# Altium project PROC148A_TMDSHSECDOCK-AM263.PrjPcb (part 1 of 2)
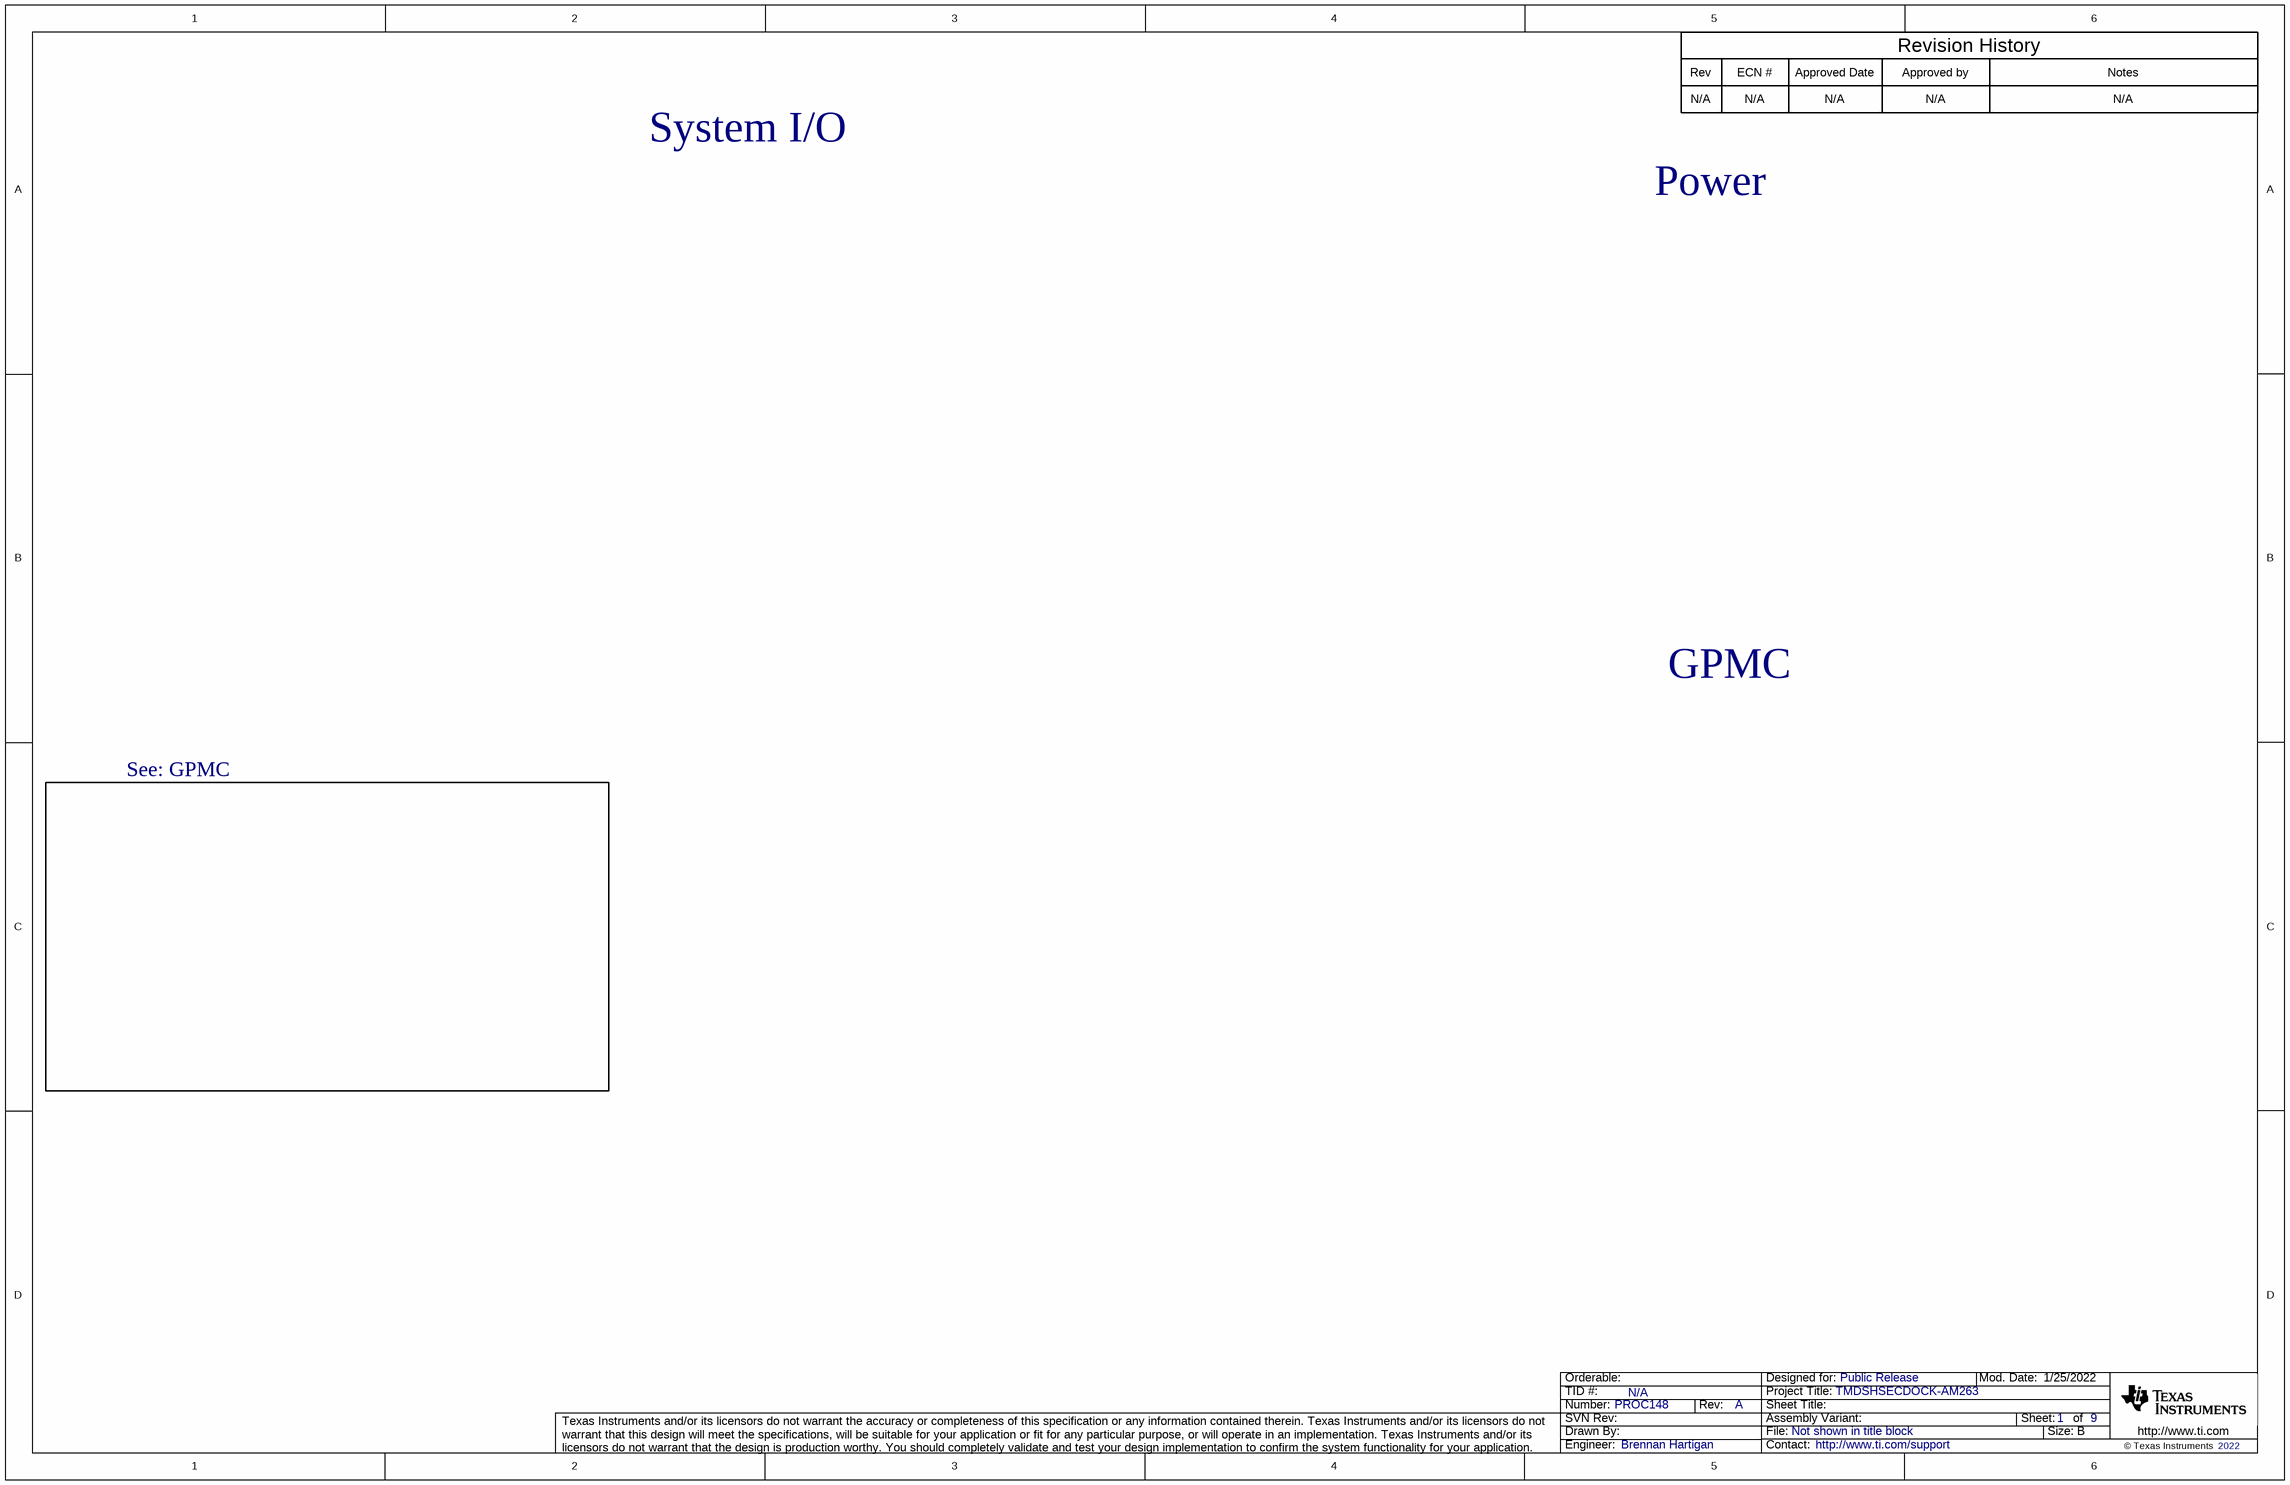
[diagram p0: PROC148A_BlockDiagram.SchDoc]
CopyrightYear: 2022; PCB_Layout: Mistral; PCB_Rev: A; PRJ_Customer: Public Release; PRJ_Engineer: Brennan Hartigan; PRJ_Number: PROC148; PRJ_Title: TMDSHSECDOCK-AM263; SCH_Rev: A; TechSupport: http://www.ti.com/support; TID: N/A
9 sheets, 287 parts. Net scope: global (net labels, ports and power ports of the same name join across sheets).
Board file: PROC148A_BRD.PcbDoc
Sheets:
  PROC148A_BlockDiagram.SchDoc
  PROC148A_PWR.SchDoc
  PROC148A_HSEC.SchDoc
  PROC148A_CAN_LIN.SchDoc
  PROC148A_HSECMUX.SchDoc
  PROC148A_PSRAM.SchDoc
  PROC148A_GPMC_interface.SchDoc
  PROC148A_JTAG_TRACE.SchDoc
  PROC148A_Hardware.SchDoc

## Sheet PROC148A_BlockDiagram.SchDoc
size 431 x 279 mm; Date: Not shown in title block; ApprovedBy: Not shown in title block; CheckedBy: Not shown in title block; Author: Not shown in title block; CompanyName: Not shown in title block; Engineer: Not shown in title block; Organization: Not shown in title block; Address1: Not shown in title block; Address2: Not shown in title block; Address3: Not shown in title block; Address4: Not shown in title block; DocumentNumber: 1; Revision: Use project parameter SCH_Rev; SheetNumber: 1; SheetTotal: 9; PageSetup: Record=PageOptions¦CenterHorizontal=True¦CenterVertical=True¦PrintScale=1.00¦XCorrection=1.00¦YCorrection=1.00¦PrintKind=0¦BorderSize=5000000¦LeftOffset=0¦BottomOffset=0¦Orientation=2¦PaperLength=1000¦PaperWidth=1000¦Scale=100¦PaperSource=15¦PrintQuality=600¦MediaType=1¦DitherType=10¦PaperKind=Letter¦PrintScaleMode=1

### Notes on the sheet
- Rev
- N/A
- ECN #
- Approved Date
- Approved by
- Revision History
- Notes
- System I/O
- Power
- GPMC
- See: GPMC

## Sheet PROC148A_PWR.SchDoc
size 431 x 279 mm; Date: Not shown in title block; ApprovedBy: Not shown in title block; CheckedBy: Not shown in title block; Author: Not shown in title block; CompanyName: Not shown in title block; Engineer: Not shown in title block; Organization: Not shown in title block; Address1: Not shown in title block; Address2: Not shown in title block; Address3: Not shown in title block; Address4: Not shown in title block; DocumentNumber: 1; Revision: Use project parameter SCH_Rev; SheetNumber: 2; SheetTotal: 9; PageSetup: Record=PageOptions¦CenterHorizontal=True¦CenterVertical=True¦PrintScale=1.00¦XCorrection=1.00¦YCorrection=1.00¦PrintKind=0¦BorderSize=5000000¦LeftOffset=0¦BottomOffset=0¦Orientation=2¦PaperLength=1000¦PaperWidth=1000¦Scale=100¦PaperSource=15¦PrintQuality=600¦MediaType=1¦DitherType=10¦PaperKind=Letter¦PrintScaleMode=1
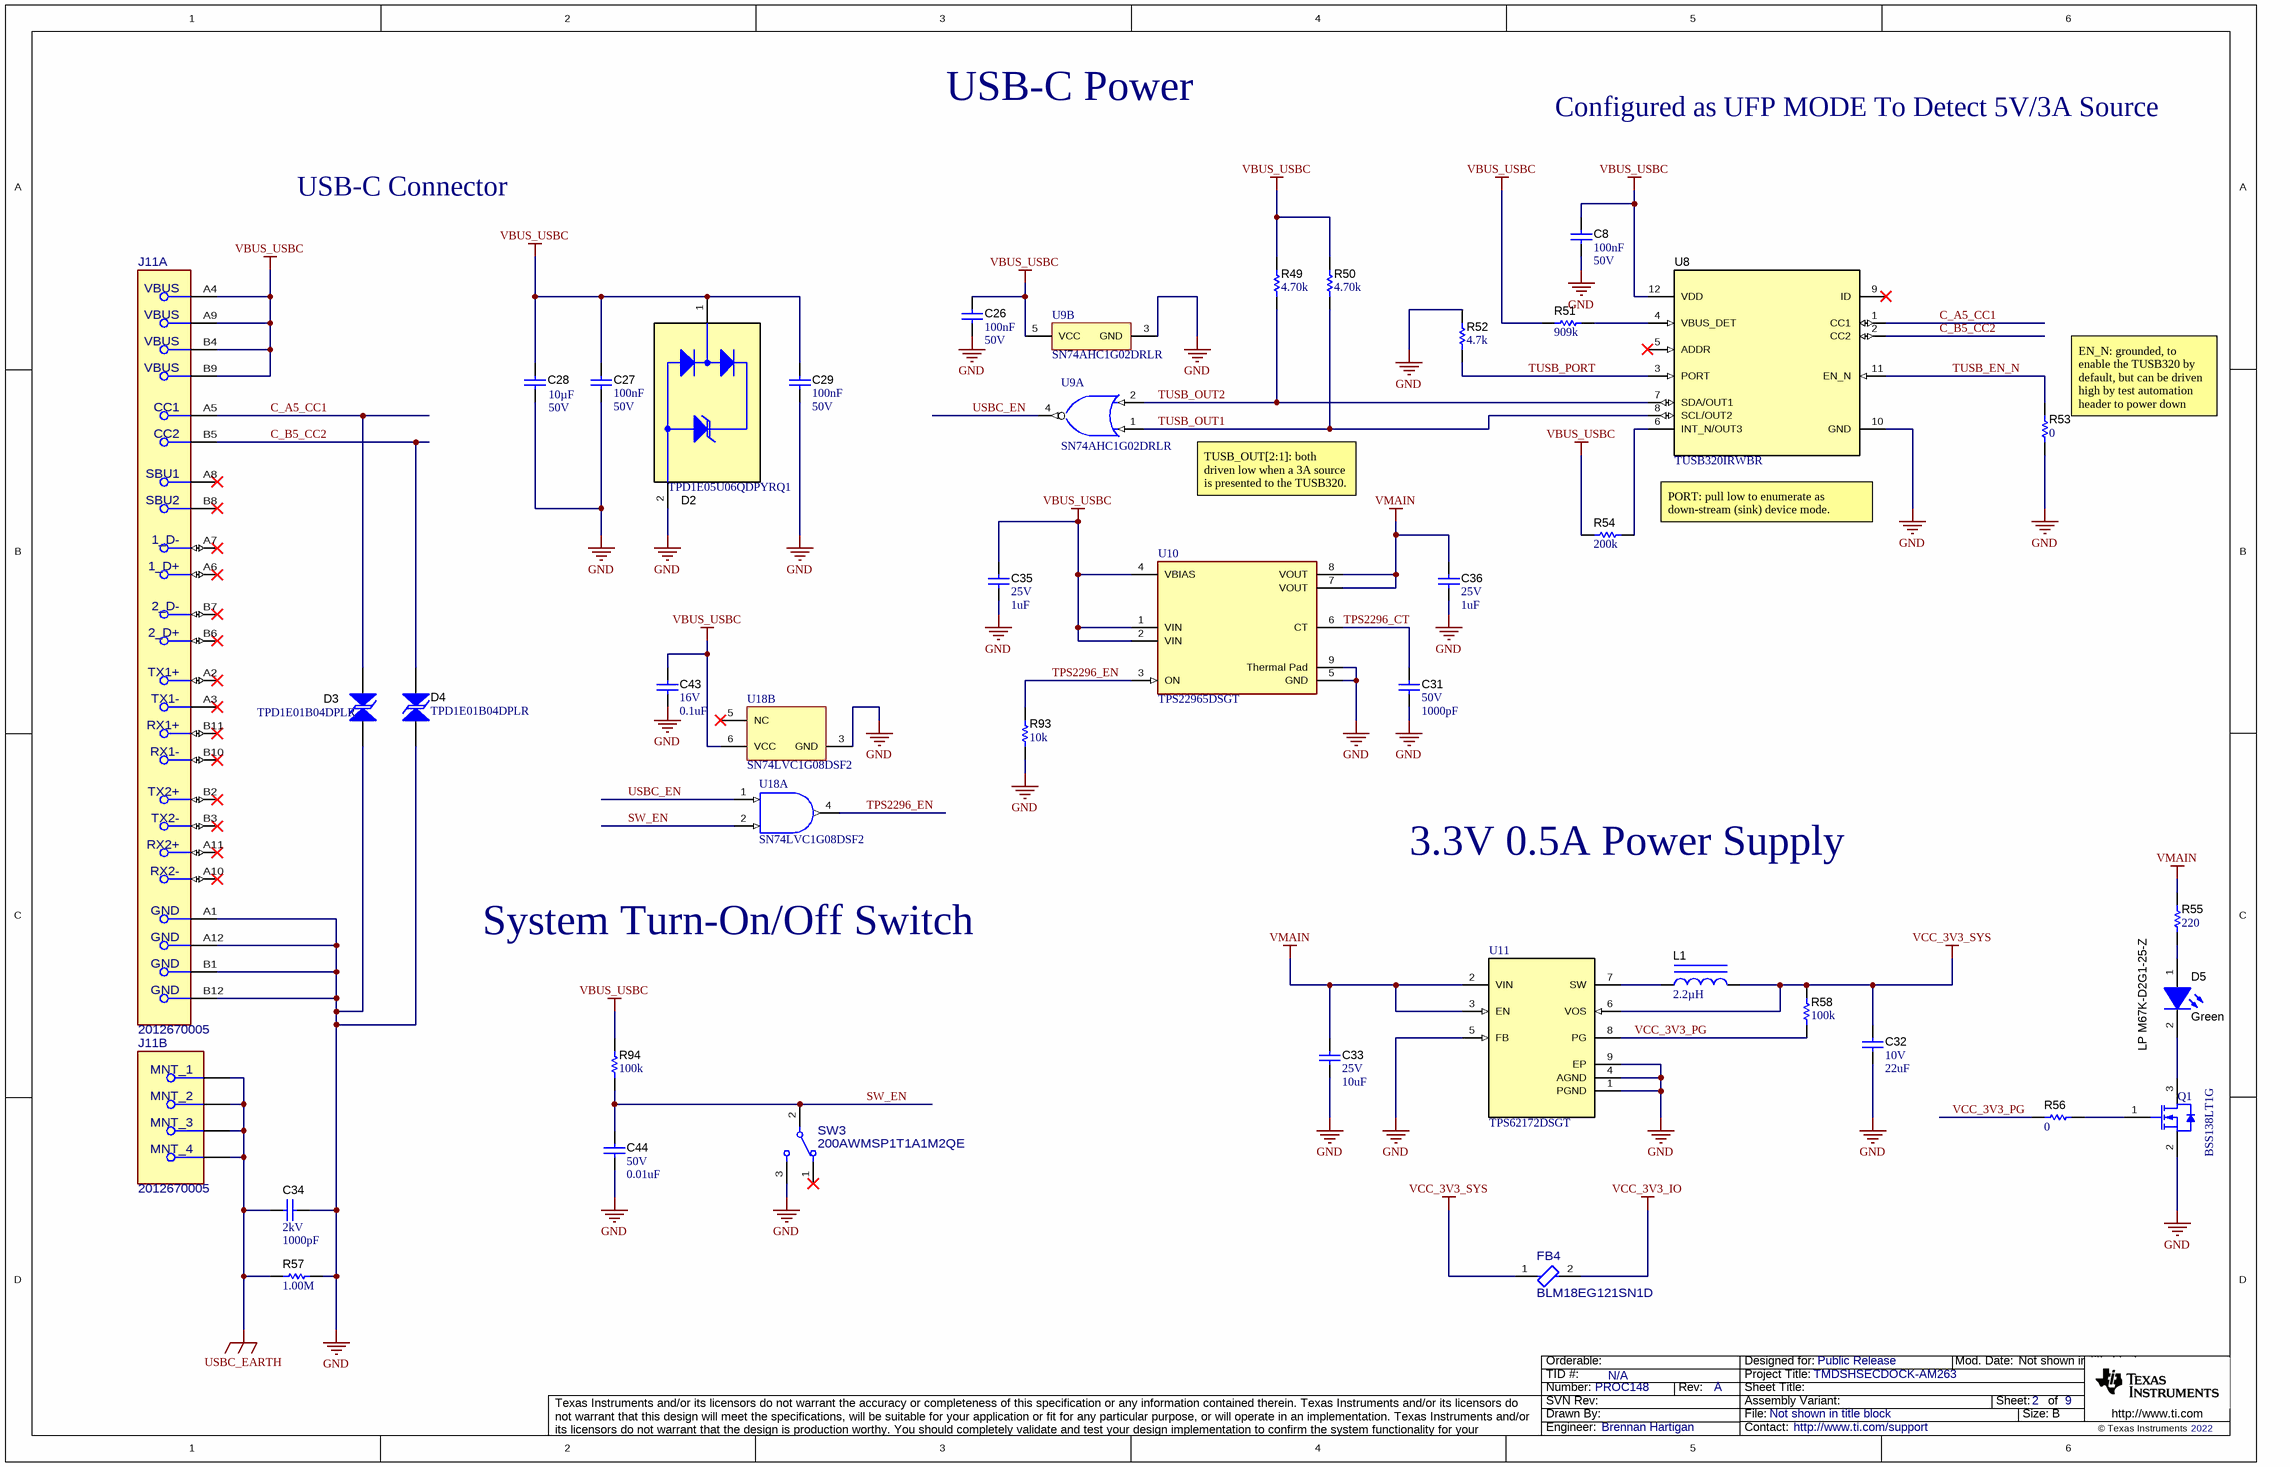
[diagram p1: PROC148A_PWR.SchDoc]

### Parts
C8  Cap_F: 100nF  VDC_V: 50V  [0805_HV]  (hidden comment: C0805C104M5RACTU)
C26  Cap_F: 100nF  VDC_V: 50V  [0805_HV]  (hidden comment: C0805C104M5RACTU)
C27  Cap_F: 100nF  VDC_V: 50V  [0805_HV]  (hidden comment: C0805C104M5RACTU)
C28  VDC_V: 50V  ValueDisplayed: 10µF  [1210_270]  (hidden comment: CL32B106KBJNNWE)
C29  Cap_F: 100nF  VDC_V: 50V  [0805_HV]  (hidden comment: C0805C104M5RACTU)
C31  VDC_V: 50V  ValueDisplayed: 1000pF  [0402]  (hidden comment: GRM1555C1H102JA01D)
C32  VDC_V: 10V  ValueDisplayed: 22uF  [1206_180]  (hidden comment: GRM31CR71A226KE15L)
C33  VDC_V: 25V  ValueDisplayed: 10uF  [0603]  (hidden comment: GRT188R61E106ME13D)
C34  VDC_V: 2kV  ValueDisplayed: 1000pF  [1808]  (hidden comment: GR442QR73D102KW01L)
C35  VDC_V: 25V  ValueDisplayed: 1uF  [0402]  (hidden comment: GRM155R61E105KA12D)
C36  VDC_V: 25V  ValueDisplayed: 1uF  [0402]  (hidden comment: GRM155R61E105KA12D)
C43  VDC_V: 16V  ValueDisplayed: 0.1uF  [0201_033]  (hidden comment: GRM033R61C104KE84D)
C44  VDC_V: 50V  ValueDisplayed: 0.01uF  [0603]  (hidden comment: GRM1885C1H103JA01D)
D2  TPD1E05U06QDPYRQ1  [DPY0002A]
D3  TPD1E01B04DPLR  [DPL0002A]
D4  TPD1E01B04DPLR  [DPL0002A]
D5  LP M67K-D2G1-25-Z  value Green  [LP-M67K_Green]
FB4  BLM18EG121SN1D  [FP-BLM18EG121SN1D_0603-MFG]
J11  2012670005  [FP-2012670005_CONN_USB_9MM39_8MM21-MFG]  (parts A,B of 2)
L1  ValueDisplayed: 2.2µH  [TFM201610ALMA]  (hidden comment: TFM201610ALMA2R2MTAA)
Q1  BSS138LT1G  [ONSC-SOT-23-3-318-08_V]
R49  ValueDisplayed: 4.70k  [0402]  (hidden comment: ERJ-2RKF4701X)
R50  ValueDisplayed: 4.70k  [0402]  (hidden comment: ERJ-2RKF4701X)
R51  ValueDisplayed: 909k  [0805_HV]  (hidden comment: ERJ-6ENF9093V)
R52  ValueDisplayed: 4.7k  [0603]  (hidden comment: CRCW06034K70JNEA)
R53  ValueDisplayed: 0  [0402]  (hidden comment: CRCW04020000Z0ED)
R54  ValueDisplayed: 200k  [0402]  (hidden comment: ERJ-2RKF2003X)
R55  ValueDisplayed: 220  [0603]  (hidden comment: CRCW0603220RJNEA)
R56  ValueDisplayed: 0  [0402]  (hidden comment: CRCW04020000Z0ED)
R57  ValueDisplayed: 1.00M  [1206]  (hidden comment: CRCW12061M00FKEA)
R58  ValueDisplayed: 100k  [0402]  (hidden comment: CRCW0402100KFKED)
R93  ValueDisplayed: 10k  [0402]  (hidden comment: CRCW040210K0JNED)
R94  ValueDisplayed: 100k  [0402]  (hidden comment: CRCW0402100KFKED)
SW3  200AWMSP1T1A1M2QE  [FP-200AWMSP1T1A1M2QE_PTH_SW_8MM13_5MM08-MFG]
U8  TUSB320IRWBR  [RWB0012A]
U9  SN74AHC1G02DRLR  [DRL0005A]  (parts A,B of 2)
U10  TPS22965DSGT  [FP-DSG0008A-MFG]
U11  TPS62172DSGT  [DSG0008A]
U18  SN74LVC1G08DSF2  [DSF0006A]  (parts A,B of 2)

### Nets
GND: C8.2 C26.2 C27.2 C28.2 C29.2 C31.2 C32.2 C33.1 C34.1 C35.2 C36.2 C43.2 C44.2 D2.2(GND) D3.1 D4.1 J11.A1(GND) J11.A12(GND) J11.B1(GND) J11.B12(GND) Q1.2(S) R52.2 R53.1 R57.2 R93.1 SW3.3 U8.10(GND) U9.3(GND) U10.5(GND) U10.9(Thermal_Pad) U11.1(PGND) U11.4(AGND) U11.5(FB) U11.9(EP) U18.3(GND)
USBC_EARTH: C34.2 J11.1(MNT_1) J11.2(MNT_2) J11.3(MNT_3) J11.4(MNT_4) R57.1
VBUS_USBC: C8.1 C26.1 C27.1 C28.1 C29.1 C35.1 C43.1 D2.1(I/O) J11.A4(VBUS) J11.A9(VBUS) J11.B4(VBUS) J11.B9(VBUS) R49.1 R50.1 R51.1 R54.1 R94.1 U8.12(VDD) U9.5(VCC) U10.1(VIN) U10.2(VIN) U10.4(VBIAS) U18.6(VCC)
VCC_3V3_IO: FB4.2
VCC_3V3_SYS: C32.1 FB4.1 L1.2 R58.1 U11.6(VOS)
VMAIN: C33.2 C36.1 R55.2 U10.7(VOUT) U10.8(VOUT) U11.2(VIN) U11.3(EN)
C_A5_CC1: D3.2 J11.A5(CC1) U8.1(CC1)
C_B5_CC2: D4.2 J11.B5(CC2) U8.2(CC2)
SW_EN: C44.1 R94.2 SW3.2(COM) U18.2(B)
TPS2296_CT: C31.1 U10.6(CT)
TPS2296_EN: R93.2 U10.3(ON) U18.4(Y)
TUSB_EN_N: R53.2 U8.11(EN_N)
TUSB_OUT1: R50.2 U8.8(SCL/OUT2) U9.1(A)
TUSB_OUT2: R49.2 U8.7(SDA/OUT1) U9.2(B)
TUSB_PORT: R52.1 U8.3(PORT)
USBC_EN: U9.4(Y) U18.1(A)
VCC_3V3_PG: R56.2 R58.2 U11.8(PG)
NetD5_1: D5.1(A) R55.1
NetD5_2: D5.2(K) Q1.3(D)
NetL1_1: L1.1 U11.7(SW)
NetQ1_1: Q1.1(G) R56.1
NetR51_2: R51.2 U8.4(VBUS_DET)
NetR54_2: R54.2 U8.6(INT_N/OUT3)

Not connected (* = marked no-connect by the designer): J11 A2(TX1+)* A3(TX1-)* A6(1_D+)* A7(1_D-)* A8(SBU1)* A10(RX2-)* A11(RX2+)* B2(TX2+)* B3(TX2-)* B6(2_D+)* B7(2_D-)* B8(SBU2)* B10(RX1-)* B11(RX1+)*; SW3 1*; U8 5(ADDR)* 9(ID)*; U18 5(NC)*

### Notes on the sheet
- USB-C Power
- Configured as UFP MODE To Detect 5V/3A Source
- USB-C Connector
- (near R53) EN_N: grounded, to enable the TUSB320 by default, but can be driven high by test automation header to power down system.
- TUSB_OUT[2:1]: both driven low when a 3A source is presented to the TUSB320.
- PORT: pull low to enumerate as down-stream (sink) device mode.
- 3.3V 0.5A Power Supply
- System Turn-On/Off Switch

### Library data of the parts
C8 C26 C27 C29 = CMP-0007727-2: CAP, CERM, 0.1 uF, 50 V, +/- 20%, X7R, 0805; Manufacturer: Kemet; TaMin_C: -55°C; ESR_ohm: 64m; Polarized: N; SizeAreaWB_mm2: 6.75; Value1: 0.064 ohm; U/M: EA; Value: 0.1uF; TaMax_C: 125°C; SizeZ_mm: 1.45; SizeX_mm: 2; SizeY_mm: 1.25; Cap_Case: 0805; SizeArea_mm2: 2.5; IRMS_A: 1.64A; AEC Category: Q200
C28 = CMP-0079201-1: CAP, CERM, 10 µF, 50 V,+/- 10%, X7R, 1210; Manufacturer: Samsung Electro-Mechanics; TaMin_C: -55°C; ESR_ohm: 5m; Polarized: N; SizeAreaWB_mm2: 14.7; Value1: 0.005 ohm; U/M: EA; Value: 10uF; TaMax_C: 125°C; SizeZ_mm: 2.7; SizeX_mm: 3.2; SizeY_mm: 2.5; Cap_Case: 1210; SizeArea_mm2: 8; AEC Category: Q200
C31 = CMP-0006412-2: CAP, CERM, 1000 pF, 50 V, +/- 5%, C0G/NP0, 0402; Manufacturer: MuRata; TaMin_C: -55°C; Polarized: N; SizeAreaWB_mm2: 3; Value1: Unknown; U/M: EA; Value: 1000pF; TaMax_C: 125°C; SizeZ_mm: 0.6; SizeX_mm: 1; SizeY_mm: 0.5; Cap_F: 1nF; AEC Category: Q200
C32 = CMP-0008959-2: CAP, CERM, 22 uF, 10 V, +/- 10%, X7R, 1206; Manufacturer: MuRata; TaMin_C: -55°C; Polarized: N; SizeAreaWB_mm2: 10.92; Value1: Unknown; U/M: EA; Value: 22uF; TaMax_C: 125°C; SizeZ_mm: 1.8; SizeX_mm: 3.2; SizeY_mm: 1.6; Cap_Case: 1206; SizeArea_mm2: 5.12; Cap_F: 22µF; AEC Category: Q200
C33 = CMP-0007501-5: CAP, CERM, 10 uF, 25 V, +/- 20%, X5R, 0603; Manufacturer: MuRata; TaMin_C: -55°C; Polarized: N; SizeAreaWB_mm2: 4.68; Value1: Unknown; U/M: EA; Value: 10uF; TaMax_C: 85°C; SizeZ_mm: 1; SizeX_mm: 1.6; SizeY_mm: 0.8; SizeArea_mm2: 1.28; Cap_F: 10µF; AEC Category: Q200
C34 = CMP-0009436-2: CAP, CERM, 1000 pF, 2000 V, +/- 10%, X7R, 1808; Manufacturer: MuRata; TaMin_C: -55°C; Polarized: N; SizeAreaWB_mm2: 16.5; Value1: Unknown; U/M: EA; Value: 1000pF; TaMax_C: 125°C; SizeZ_mm: 2.03; SizeX_mm: 4.5; SizeY_mm: 2; Value2: 2000V; SizeArea_mm2: 9; Cap_F: 1nF; AEC Category: Q200
C35 C36 = CMP-0006608-2: CAP, CERM, 1 uF, 25 V, +/- 10%, X5R, 0402; Manufacturer: MuRata; TaMin_C: -55°C; Polarized: N; SizeAreaWB_mm2: 3; Value1: Unknown; U/M: EA; Value: 1uF; TaMax_C: 85°C; SizeZ_mm: 0.6; SizeX_mm: 1; SizeY_mm: 0.5; Cap_F: 1µF; AEC Category: Q200
C43 = CMP-0009717-2: CAP, CERM, 0.1 uF, 16 V, +/- 10%, X5R, 0201; Manufacturer: MuRata; TaMin_C: -55°C; Polarized: N; SizeAreaWB_mm2: 2.08; Value1: Unknown; U/M: EA; Value: 0.1uF; TaMax_C: 85°C; SizeZ_mm: 0.33; SizeX_mm: 0.6; SizeY_mm: 0.3; Cap_Case: 0201; SizeArea_mm2: 0.18; Cap_F: 100nF; AEC Category: Q200
C44 = CMP-0007174-4: CAP, CERM, 0.01 uF, 50 V, +/- 5%, C0G/NP0, 0603; Manufacturer: MuRata; TaMin_C: -55°C; Polarized: N; SizeAreaWB_mm2: 4.68; Value1: Unknown; U/M: EA; Value: 0.01uF; TaMax_C: 125°C; SizeZ_mm: 1; SizeX_mm: 1.6; SizeY_mm: 0.8; SizeArea_mm2: 1.28; Cap_F: 10nF; AEC Category: Q200
D2 = CMP-0073591-4: Automotive 1-Channel Ultra-Low-Capacitance IEC ESD Protection Diode, DPY0002A (X1SON-2); Alternate Manufacturer: Texas Instruments; Alternate PartNumber: TPD1E05U06QDPYTQ1; SizeZ_mm: 0.45; SizeAreaWB_mm2: 3.2; SizeArea_mm2: 0.6; CompType: IC; AEC Category: Q200; AEC Qualified: Y; SizeX_mm: 1.0
D3 D4 = CMP-0073601-1: 1-Channel ESD Protection Diode for USB Type-C and Thunderbolt 3, DPL0002A (X2SON-2); Alternate PartNumber: TPD1E01B04DPLT; Alternate Manufacturer: Texas Instruments; SizeAreaWB_mm2: 2.08; U/M: EA; SizeZ_mm: 0.32; SizeX_mm: 0.6; SizeY_mm: 0.3; SizeArea_mm2: 0.18; CompType: IC
D5 = CMP-0002879-2: LED, Green, SMD; Manufacturer: OSRAM; Io_A: 20mA; Tjmax_C: 125°C; Value1: W; Vf_V: 1.8V; RJC_CperW: 28
FB4 = CMP-0089199-1: 120 Ohms @ 100MHz 1  Ferrite Bead 0603 (1608 Metric) 2A 40mOhm; Manufacturer: Murata; DCR_ohm: 60m; AEC Qualified: No; Tolerance_%: 25%; SizeZ_mm: 0.95mm; Impedance At Frequency: 120Ω @ 100MHz
J11 = CMP-0093552-1: USB-C (USB TYPE-C) USB 3.2 Gen 2 (USB 3.1 Gen 2, Superspeed + (USB 3.1)) Receptacle Connector 24 Position Surface Mount, Right Angle; Through Hole; Manufacturer: Molex; Voltage_V: 30V; SizeZ_mm: 3.86mm; DUT-Pitch_mm: 0.5mm; Shrouded: true; ContactFinish: Gold,Nickel; Usb Standard: USB 3.1; AEC Qualified: No; Is Female: yes
L1 = CMP-0081094-1: Inductor, Shielded, Metal Composite, 2.2 µH, 1.9 A, 0.152 ohm, AEC-Q200 Grade 0, SMD; Manufacturer: TDK; Isat: 2A @ 30% inductance drop; Irms: 1.9A @ 40C rise; SizeAreaWB_mm2: 7.8; DCR_ohm: 0.152; Value: 2.2uH; Imax_A: 1.9A; SizeZ_mm: 1; SizeX_mm: 2; SizeY_mm: 1.6; SizeArea_mm2: 3.2; AEC Qualified: Y; AEC Grade: 0; AEC Category: Q200
Q1 = CMP-1058-00767-1: Power MOSFET, 200 mA, 50 V, N-Channel, 3-Pin SOT-23, Pb-Free, Tape and Reel; Manufacturer: On Semiconductor; PD Max (W): 0.225; Coss Typ (pF): 12; V(BR)DSS Min (V): 50; VGS Max (V): 20; Channel Polarity: N Channel; Configuration: Single; VGS(th) Max (V): 1.5; Ciss Typ (pF): 40; Crss Typ (pF): 3.5; ID Max (A): 0.2
R49 R50 = CMP-0026700-1: RES, 4.70 k, 1%, 0.1 W, 0402; Manufacturer: Panasonic; Power_W: 100mW; TempCo: 100 ppm/C; Value_Code: 4k70; U/M: EA; Value: 4.70k; Res_ohm: 4.7k; SizeX_mm: 1; SizeY_mm: 0.5; SizeZ_mm: 0.6; Value2: 0.1W; VDC_V: 50V; AEC Category: Q200
R51 = CMP-0021811-3: RES, 909 k, 1%, 0.125 W, AEC-Q200 Grade 0, 0805; Manufacturer: Panasonic; Power_W: 125mW; TempCo: 100 ppm/C; Value: 909k; EIA_Code: E96; SizeX_mm: 2; SizeY_mm: 1.25; SizeZ_mm: 1.45; Value2: 0.125W; SizeArea_mm2: 2.5; AEC Qualified: Y; AEC Category: Q200; AEC Grade: 0; SizeAreaWB_mm2: 6.75
R52 = CMP-0025817-4: RES, 4.7 k, 5%, 0.1 W, AEC-Q200 Grade 0, 0603; Manufacturer: Vishay-Dale; Power_W: 100mW; TempCo: 200 ppm/C; Value_Code: 4k70; Value: 4.7k; EIA_Code: E24; SizeX_mm: 1.6; SizeY_mm: 0.8; SizeZ_mm: 1; Value2: 0.1W; SizeArea_mm2: 1.28; AEC Qualified: Y; VDC_V: 75V; AEC Category: Q200; AEC Grade: 0
R53 R56 = CMP-0026822-3: RES, 0, 5%, 0.063 W, AEC-Q200 Grade 0, 0402; Manufacturer: Vishay-Dale; Power_W: 63mW; TempCo: 200 ppm/C; Value_Code: 0000; Value: 0; EIA_Code: E24; SizeX_mm: 1; SizeY_mm: 0.5; SizeZ_mm: 0.6; Value2: 0.063W; AEC Qualified: Y; VDC_V: 50V; AEC Category: Q200
R54 = CMP-0026677-1: RES, 200 k, 1%, 0.1 W, 0402; Manufacturer: Panasonic; Power_W: 100mW; TempCo: 100 ppm/C; U/M: EA; Value: 200k; EIA_Code: E96; SizeX_mm: 1; SizeY_mm: 0.5; SizeZ_mm: 0.6; Value2: 0.1W; VDC_V: 50V; AEC Category: Q200
R55 = CMP-0025756-4: RES, 220, 5%, 0.1 W, AEC-Q200 Grade 0, 0603; Manufacturer: Vishay-Dale; Power_W: 100mW; TempCo: 200 ppm/C; Value_Code: 220R; Value: 220; EIA_Code: E24; SizeX_mm: 1.6; SizeY_mm: 0.8; SizeZ_mm: 1; Value2: 0.1W; SizeArea_mm2: 1.28; AEC Qualified: Y; VDC_V: 75V; AEC Category: Q200; AEC Grade: 0
R57 = CMP-0016716-3: RES, 1.00 M, 1%, 0.25 W, AEC-Q200 Grade 0, 1206; Manufacturer: Vishay-Dale; Power_W: 250mW; TempCo: 100 ppm/C; Value_Code: 1M00; Value: 1.00Meg; EIA_Code: E96; Res_ohm: 1M; SizeX_mm: 3.2; SizeY_mm: 1.6; SizeZ_mm: 1.35; Value2: 0.25W; SizeArea_mm2: 5.12; AEC Qualified: Y; VDC_V: 200V; AEC Category: Q200; AEC Grade: 0
R58 R94 = CMP-0025950-3: RES, 100 k, 1%, 0.063 W, AEC-Q200 Grade 0, 0402; Manufacturer: Vishay-Dale; Power_W: 63mW; TempCo: 100 ppm/C; Value: 100k; EIA_Code: E96; SizeX_mm: 1; SizeY_mm: 0.5; SizeZ_mm: 0.6; Value2: 0.063W; AEC Qualified: Y; VDC_V: 50V; AEC Category: Q200; AEC Grade: 0
R93 = CMP-0026825-5: RES, 10 k, 5%, 0.063 W, AEC-Q200 Grade 0, 0402; Manufacturer: Vishay-Dale; Power_W: 63mW; TempCo: 200 ppm/C; Value_Code: 10k0; Value: 10k; EIA_Code: E24; SizeX_mm: 1; SizeY_mm: 0.5; SizeZ_mm: 0.6; Value2: 0.063W; AEC Qualified: Y; VDC_V: 50V; AEC Category: Q200; AEC Grade: 0
SW3 = CMP-0091791-1: Toggle Switch SPDT Through Hole  3A 120V; Manufacturer: E-Switch; VDC_V: 28V; AEC Qualified: No; Electromechanical Life: 50000Cycles; SizeZ_mm: 24.2mm
U8 = CMP-0073634-2: USB Type-C  for USB 2.0 CC Port Controller, RWB0012A (X2QFN-12); Alternate Manufacturer: Texas Instruments; SizeAreaWB_mm2: 6.76; SizeZ_mm: 0.4; SizeX_mm: 1.6; SizeArea_mm2: 2.56; CompType: IC; AEC Category: Q200; AEC Qualified: N; Rating: Catalog
U9 = CMP-0051530-2: Single 2-Input Positive-NOR Gate, DRL0005A, LARGE T&R; Manufacturer: Texas Instruments; Schmitt Trigger: No; Technology Family: AHC; Logic: True; Gate Type: NOR; Output Type: CMOS; Sub-Family: NAND Gate; Rating: Catalog; F @ Nom Voltage(Max)(Mhz): 75; ICC @ Nom Voltage(Max)(mA): 0.01; tpd @ Nom Voltage(Max)(ns): 11.4,7.5; Voltage(Nom)(V): 3.3,5; Output Drive (IOL/IOH)(Max)(mA): 50/-50; VCC(Max)(V): 5.5; VCC(Min)(V): 2; Bits(#): 1; AEC Category: Q200; AEC Qualified: N; CompType: IC; SizeArea_mm2: 2.56; SizeX_mm: 1.6; SizeZ_mm: 0.6
U10 = CMP-04913-000004-1: IC PWR SWITCH N-CHAN 1:1 8WSON; Manufacturer: Texas Instruments; Nominal Supply Current: 20-50uA; Number Of Outputs: 1; Turn Off Delay Time: 9us; Turn On Delay Time: 730us; On State Resistance: 16mΩ; Min Supply Voltage: 2.5V; Max Junction Temp: +125°C; Output Current: 6A; Max Supply Voltage: 5.7V; Standoff Height: 0mm; Output Voltage: 0.8-5.7V
U11 = CMP-0037798-2: Buck Step Down Regulator with 3 to 17 V Input and 3.3 V Output, -40 to 85 degC, 8-Pin WSON (DSG), Green (RoHS & no Sb/Br); Manufacturer: Texas Instruments; Vin(Min)(V): 3; Switch Current Limit(Typ)(A): 1.05; Vin(Max)(V): 17; Rating: Catalog; Vout(Min)(V): 3.3; Regulated Outputs(#): 1; Duty Cycle(Max)(%): 100; SubFamily: Step-Down Regulator; Synchronous Rectification: TRUE; Iq(Typ)(mA): 0.017; Iout(Max)(A): 0.5
U18 = CMP-0051419-5: Single 2-Input Positive-AND Gate, DSF0006A, LARGE T&R; Manufacturer: Texas Instruments; Output Type: CMOS; Bits(#): 1; Input Type: CMOS/TTL; Technology Family: LVC; Schmitt Trigger: No; VCC(Max)(V): 5.5; Gate Type: AND; Rating: Catalog; Output Drive (IOL/IOH)(Max)(mA): 32/-32; ICC @ Nom Voltage(Max)(mA): 0.01; VCC(Min)(V): 1.65; F @ Nom Voltage(Max)(Mhz): 150; Logic: True; Voltage(Nom)(V): 1.8,2.5,3.3,5; tpd @ Nom Voltage(Max)(ns): 4.5,6,4,5; AEC Category: Q200; AEC Qualified: N; CompType: IC

## Sheet PROC148A_HSEC.SchDoc
size 558 x 431 mm; Date: Not shown in title block; ApprovedBy: Not shown in title block; CheckedBy: Not shown in title block; Author: Not shown in title block; CompanyName: Not shown in title block; Engineer: Not shown in title block; Organization: Not shown in title block; Address1: Not shown in title block; Address2: Not shown in title block; Address3: Not shown in title block; Address4: Not shown in title block; DocumentNumber: 2; Revision: Use project parameter SCH_Rev; SheetNumber: 3; SheetTotal: 9; PageSetup: Record=PageOptions¦CenterHorizontal=True¦CenterVertical=True¦PrintScale=1.00¦XCorrection=1.00¦YCorrection=1.00¦PrintKind=0¦BorderSize=5000000¦LeftOffset=0¦BottomOffset=0¦Orientation=2¦PaperLength=1000¦PaperWidth=1000¦Scale=100¦PaperSource=15¦PrintQuality=600¦MediaType=1¦DitherType=10¦PaperKind=Letter¦PrintScaleMode=1
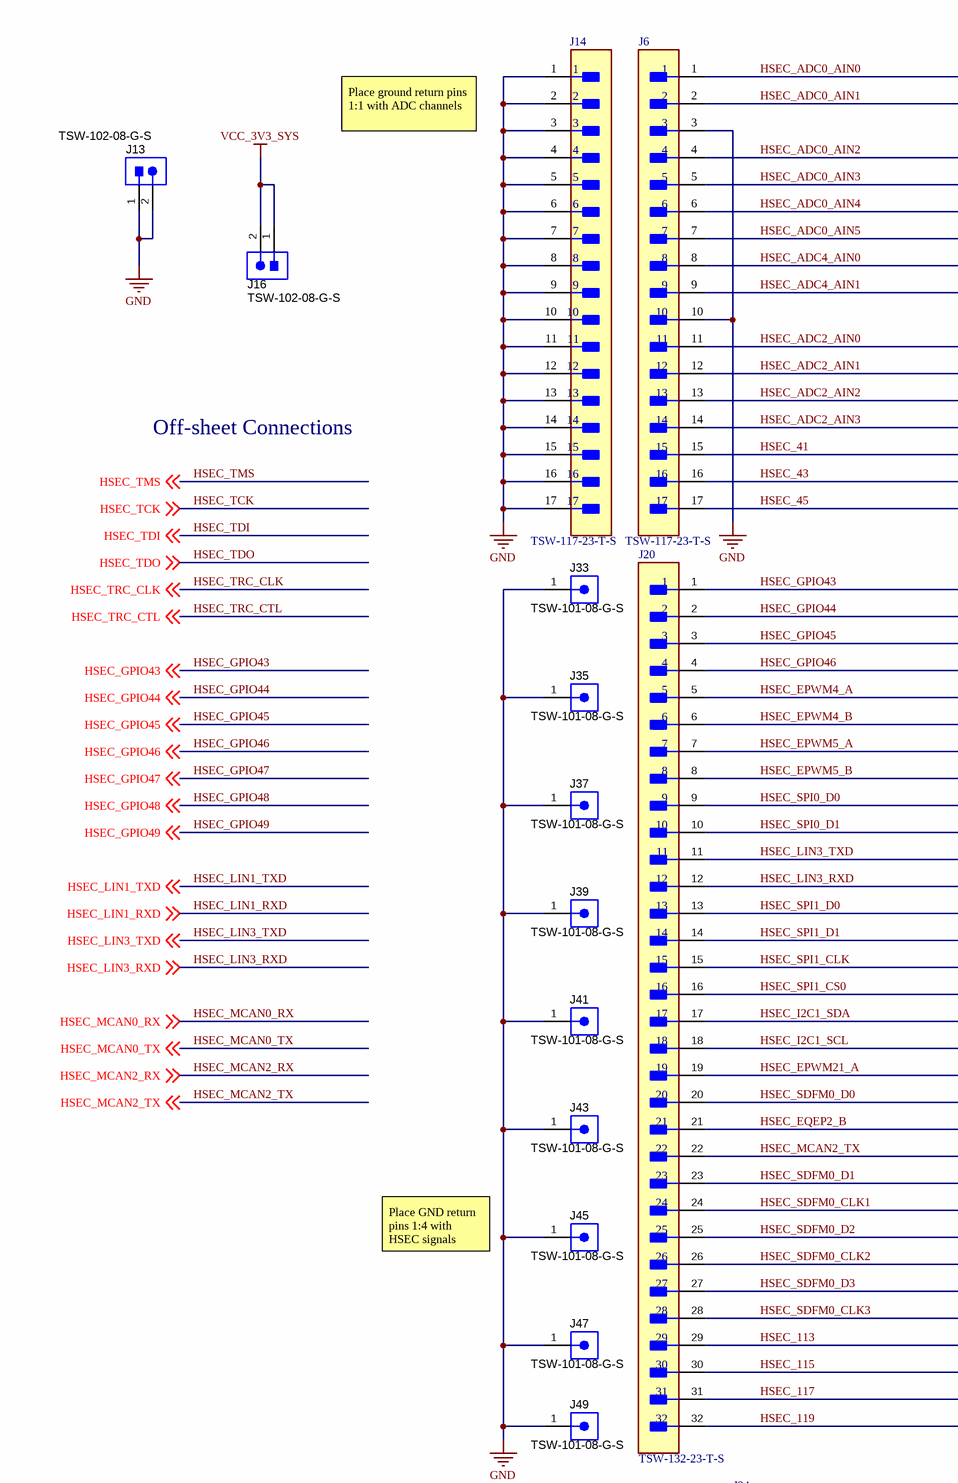
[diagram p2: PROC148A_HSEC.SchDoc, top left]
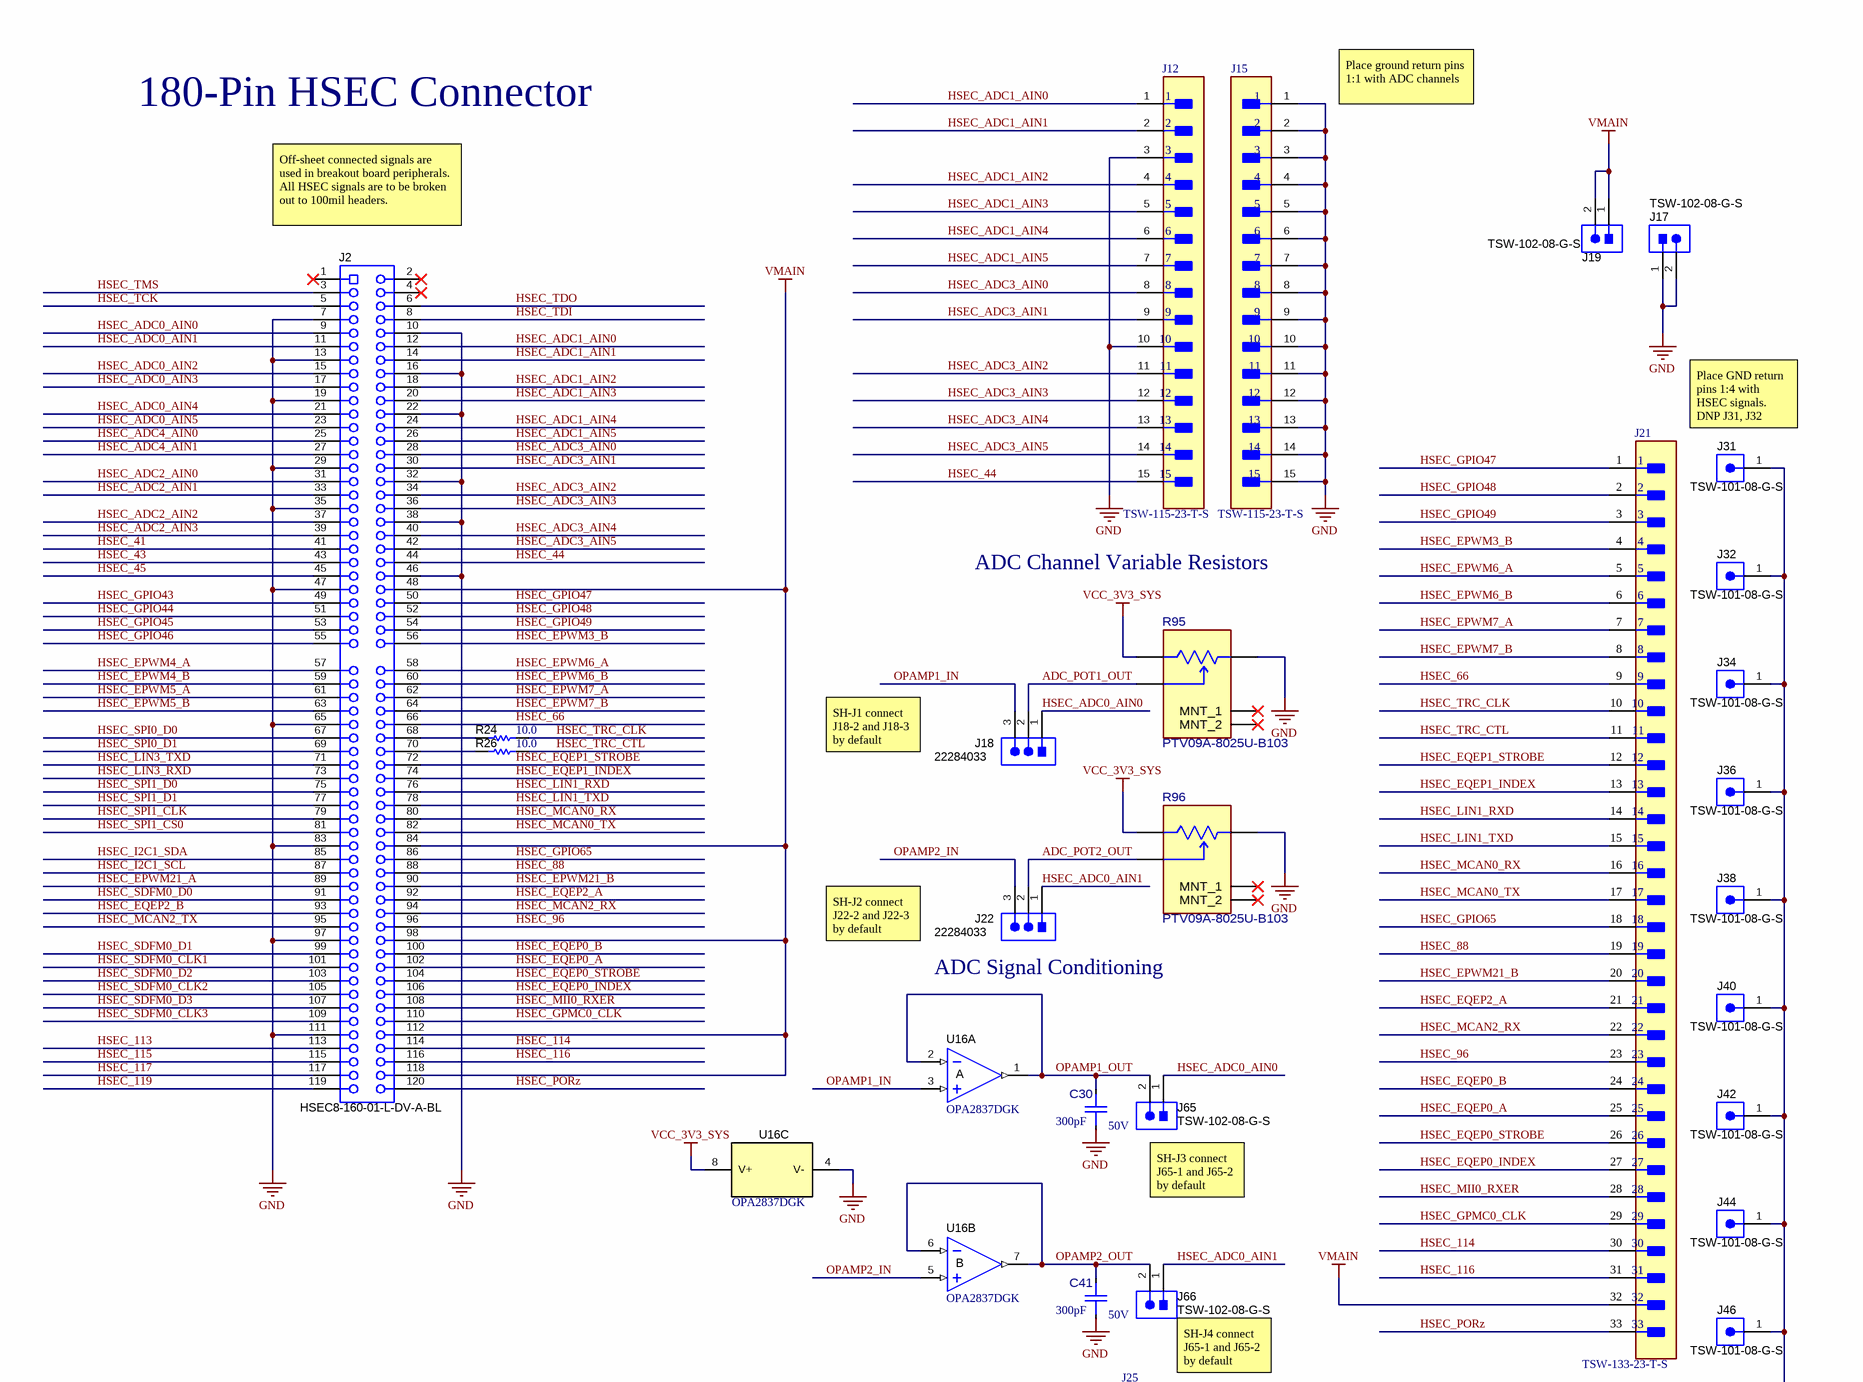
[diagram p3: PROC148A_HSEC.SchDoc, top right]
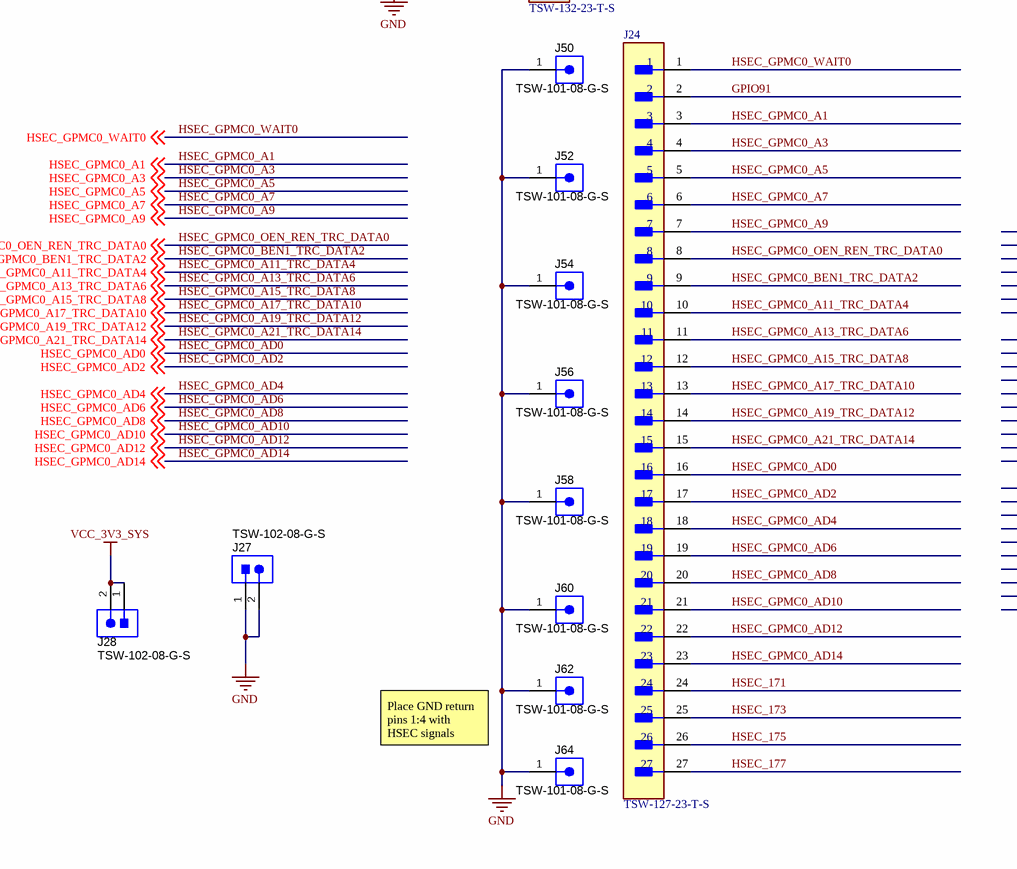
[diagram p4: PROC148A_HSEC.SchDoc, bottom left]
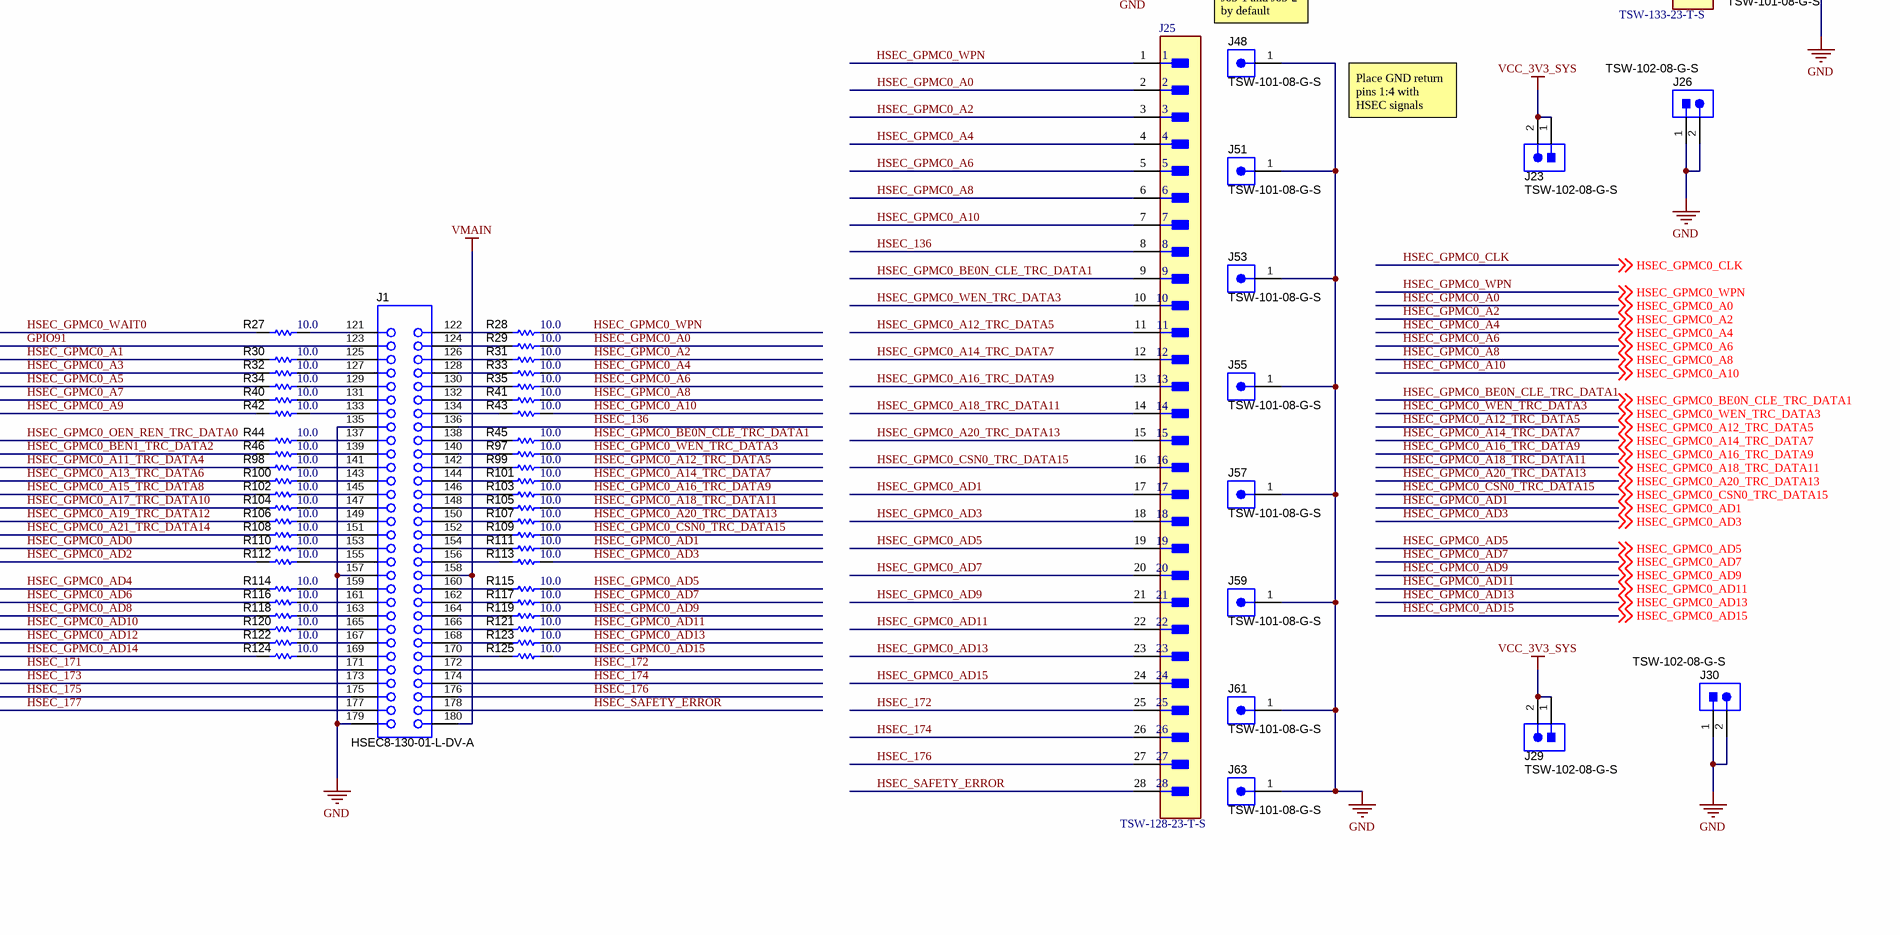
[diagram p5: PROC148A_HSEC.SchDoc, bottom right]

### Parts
C30  ValueDisplayed: 300pF  VDC_V: 50V  [FP-C0603C301J5GAC7867_0603-MFG]  (hidden comment: C0603C301J5GAC7867)
C41  ValueDisplayed: 300pF  VDC_V: 50V  [FP-C0603C301J5GAC7867_0603-MFG]  (hidden comment: C0603C301J5GAC7867)
J1  HSEC8-130-01-L-DV-A  [controlCARD-180HSEC-60pinAddon]
J2  HSEC8-160-01-L-DV-A-BL  [controlCARD-120HSEC]
J6  TSW-117-23-T-S  [FP-TSW-117-23-T-S-MFG]
J12  TSW-115-23-T-S  [FP-TSW-115-23-T-S-MFG]
J13  TSW-102-08-G-S  [Samtec_TSW-102-08-x-S]
J14  TSW-117-23-T-S  [FP-TSW-117-23-T-S-MFG]
J15  TSW-115-23-T-S  [FP-TSW-115-23-T-S-MFG]
J16  TSW-102-08-G-S  [Samtec_TSW-102-08-x-S]
J17  TSW-102-08-G-S  [Samtec_TSW-102-08-x-S]
J18  22284033  [Molex_0022284033]
J19  TSW-102-08-G-S  [Samtec_TSW-102-08-x-S]
J20  TSW-132-23-T-S  [FP-TSW-132-23-T-S-MFG]
J21  TSW-133-23-T-S  [FP-TSW-133-23-T-S-MFG]
J22  22284033  [Molex_0022284033]
J23  TSW-102-08-G-S  [Samtec_TSW-102-08-x-S]
J24  TSW-127-23-T-S  [FP-TSW-127-23-T-S-MFG]
J25  TSW-128-23-T-S  [FP-TSW-128-23-T-S-0]
J26  TSW-102-08-G-S  [Samtec_TSW-102-08-x-S]
J27  TSW-102-08-G-S  [Samtec_TSW-102-08-x-S]
J28  TSW-102-08-G-S  [Samtec_TSW-102-08-x-S]
J29  TSW-102-08-G-S  [Samtec_TSW-102-08-x-S]
J30  TSW-102-08-G-S  [Samtec_TSW-102-08-x-S]
J31  TSW-101-08-G-S  [Samtec_TSW-101-08-x-S]
J32  TSW-101-08-G-S  [Samtec_TSW-101-08-x-S]
J33  TSW-101-08-G-S  [Samtec_TSW-101-08-x-S]
J34  TSW-101-08-G-S  [Samtec_TSW-101-08-x-S]
J35  TSW-101-08-G-S  [Samtec_TSW-101-08-x-S]
J36  TSW-101-08-G-S  [Samtec_TSW-101-08-x-S]
J37  TSW-101-08-G-S  [Samtec_TSW-101-08-x-S]
J38  TSW-101-08-G-S  [Samtec_TSW-101-08-x-S]
J39  TSW-101-08-G-S  [Samtec_TSW-101-08-x-S]
J40  TSW-101-08-G-S  [Samtec_TSW-101-08-x-S]
J41  TSW-101-08-G-S  [Samtec_TSW-101-08-x-S]
J42  TSW-101-08-G-S  [Samtec_TSW-101-08-x-S]
J43  TSW-101-08-G-S  [Samtec_TSW-101-08-x-S]
J44  TSW-101-08-G-S  [Samtec_TSW-101-08-x-S]
J45  TSW-101-08-G-S  [Samtec_TSW-101-08-x-S]
J46  TSW-101-08-G-S  [Samtec_TSW-101-08-x-S]
J47  TSW-101-08-G-S  [Samtec_TSW-101-08-x-S]
J48  TSW-101-08-G-S  [Samtec_TSW-101-08-x-S]
J49  TSW-101-08-G-S  [Samtec_TSW-101-08-x-S]
J50  TSW-101-08-G-S  [Samtec_TSW-101-08-x-S]
J51  TSW-101-08-G-S  [Samtec_TSW-101-08-x-S]
J52  TSW-101-08-G-S  [Samtec_TSW-101-08-x-S]
J53  TSW-101-08-G-S  [Samtec_TSW-101-08-x-S]
J54  TSW-101-08-G-S  [Samtec_TSW-101-08-x-S]
J55  TSW-101-08-G-S  [Samtec_TSW-101-08-x-S]
J56  TSW-101-08-G-S  [Samtec_TSW-101-08-x-S]
J57  TSW-101-08-G-S  [Samtec_TSW-101-08-x-S]
J58  TSW-101-08-G-S  [Samtec_TSW-101-08-x-S]
J59  TSW-101-08-G-S  [Samtec_TSW-101-08-x-S]
J60  TSW-101-08-G-S  [Samtec_TSW-101-08-x-S]
J61  TSW-101-08-G-S  [Samtec_TSW-101-08-x-S]
J62  TSW-101-08-G-S  [Samtec_TSW-101-08-x-S]
J63  TSW-101-08-G-S  [Samtec_TSW-101-08-x-S]
J64  TSW-101-08-G-S  [Samtec_TSW-101-08-x-S]
J65  TSW-102-08-G-S  [Samtec_TSW-102-08-x-S]
J66  TSW-102-08-G-S  [Samtec_TSW-102-08-x-S]
R24  ValueDisplayed: 10.0  [0201]  (hidden comment: RC0201FR-0710RL)
R26  ValueDisplayed: 10.0  [0201]  (hidden comment: RC0201FR-0710RL)
R27  ValueDisplayed: 10.0  [0201]  (hidden comment: RC0201FR-0710RL)
R28  ValueDisplayed: 10.0  [0201]  (hidden comment: RC0201FR-0710RL)
R29  ValueDisplayed: 10.0  [0201]  (hidden comment: RC0201FR-0710RL)
R30  ValueDisplayed: 10.0  [0201]  (hidden comment: RC0201FR-0710RL)
R31  ValueDisplayed: 10.0  [0201]  (hidden comment: RC0201FR-0710RL)
R32  ValueDisplayed: 10.0  [0201]  (hidden comment: RC0201FR-0710RL)
R33  ValueDisplayed: 10.0  [0201]  (hidden comment: RC0201FR-0710RL)
R34  ValueDisplayed: 10.0  [0201]  (hidden comment: RC0201FR-0710RL)
R35  ValueDisplayed: 10.0  [0201]  (hidden comment: RC0201FR-0710RL)
R40  ValueDisplayed: 10.0  [0201]  (hidden comment: RC0201FR-0710RL)
R41  ValueDisplayed: 10.0  [0201]  (hidden comment: RC0201FR-0710RL)
R42  ValueDisplayed: 10.0  [0201]  (hidden comment: RC0201FR-0710RL)
R43  ValueDisplayed: 10.0  [0201]  (hidden comment: RC0201FR-0710RL)
R44  ValueDisplayed: 10.0  [0201]  (hidden comment: RC0201FR-0710RL)
R45  ValueDisplayed: 10.0  [0201]  (hidden comment: RC0201FR-0710RL)
R46  ValueDisplayed: 10.0  [0201]  (hidden comment: RC0201FR-0710RL)
R95  PTV09A-8025U-B103  [FP-PTV09A-8025U-B103_PTH_POT_27MM4_9MM7-MFG]
R96  PTV09A-8025U-B103  [FP-PTV09A-8025U-B103_PTH_POT_27MM4_9MM7-MFG]
R97  ValueDisplayed: 10.0  [0201]  (hidden comment: RC0201FR-0710RL)
R98  ValueDisplayed: 10.0  [0201]  (hidden comment: RC0201FR-0710RL)
R99  ValueDisplayed: 10.0  [0201]  (hidden comment: RC0201FR-0710RL)
R100  ValueDisplayed: 10.0  [0201]  (hidden comment: RC0201FR-0710RL)
R101  ValueDisplayed: 10.0  [0201]  (hidden comment: RC0201FR-0710RL)
R102  ValueDisplayed: 10.0  [0201]  (hidden comment: RC0201FR-0710RL)
R103  ValueDisplayed: 10.0  [0201]  (hidden comment: RC0201FR-0710RL)
R104  ValueDisplayed: 10.0  [0201]  (hidden comment: RC0201FR-0710RL)
R105  ValueDisplayed: 10.0  [0201]  (hidden comment: RC0201FR-0710RL)
R106  ValueDisplayed: 10.0  [0201]  (hidden comment: RC0201FR-0710RL)
R107  ValueDisplayed: 10.0  [0201]  (hidden comment: RC0201FR-0710RL)
R108  ValueDisplayed: 10.0  [0201]  (hidden comment: RC0201FR-0710RL)
R109  ValueDisplayed: 10.0  [0201]  (hidden comment: RC0201FR-0710RL)
R110  ValueDisplayed: 10.0  [0201]  (hidden comment: RC0201FR-0710RL)
R111  ValueDisplayed: 10.0  [0201]  (hidden comment: RC0201FR-0710RL)
R112  ValueDisplayed: 10.0  [0201]  (hidden comment: RC0201FR-0710RL)
R113  ValueDisplayed: 10.0  [0201]  (hidden comment: RC0201FR-0710RL)
R114  ValueDisplayed: 10.0  [0201]  (hidden comment: RC0201FR-0710RL)
R115  ValueDisplayed: 10.0  [0201]  (hidden comment: RC0201FR-0710RL)
R116  ValueDisplayed: 10.0  [0201]  (hidden comment: RC0201FR-0710RL)
R117  ValueDisplayed: 10.0  [0201]  (hidden comment: RC0201FR-0710RL)
R118  ValueDisplayed: 10.0  [0201]  (hidden comment: RC0201FR-0710RL)
R119  ValueDisplayed: 10.0  [0201]  (hidden comment: RC0201FR-0710RL)
R120  ValueDisplayed: 10.0  [0201]  (hidden comment: RC0201FR-0710RL)
R121  ValueDisplayed: 10.0  [0201]  (hidden comment: RC0201FR-0710RL)
R122  ValueDisplayed: 10.0  [0201]  (hidden comment: RC0201FR-0710RL)
R123  ValueDisplayed: 10.0  [0201]  (hidden comment: RC0201FR-0710RL)
R124  ValueDisplayed: 10.0  [0201]  (hidden comment: RC0201FR-0710RL)
R125  ValueDisplayed: 10.0  [0201]  (hidden comment: RC0201FR-0710RL)
U16  OPA2837DGK  [DGK0008A_N]  (parts A,B,C of 3)

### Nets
GND: C30.1 C41.1 J1.135 J1.157 J1.179 J2.7 J2.10 J2.13 J2.16 J2.19 J2.22 J2.29 J2.32 J2.35 J2.38 J2.46 J2.47 J2.65 J2.83 J2.97 J2.111 J6.3 J6.10 J12.3 J12.10 J13.1 J13.2 J14.1 J14.2 J14.3 J14.4 J14.5 J14.6 J14.7 J14.8 J14.9 J14.10 J14.11 J14.12 J14.13 J14.14 J14.15 J14.16 J14.17 J15.1 J15.2 J15.3 J15.4 J15.5 J15.6 J15.7 J15.8 J15.9 J15.10 J15.11 J15.12 J15.13 J15.14 J15.15 J17.1 J17.2 J26.1 J26.2 J27.1 J27.2 J30.1 J30.2 J31.1 J32.1 J33.1 J34.1 J35.1 J36.1 J37.1 J38.1 J39.1 J40.1 J41.1 J42.1 J43.1 J44.1 J45.1 J46.1 J47.1 J48.1 J49.1 J50.1 J51.1 J52.1 J53.1 J54.1 J55.1 J56.1 J57.1 J58.1 J59.1 J60.1 J61.1 J62.1 J63.1 J64.1 R95.3 R96.3 U16.4(V-)
VCC_3V3_SYS: J16.1 J16.2 J23.1 J23.2 J28.1 J28.2 J29.1 J29.2 R95.1 R96.1 U16.8(V+)
VMAIN: J1.158 J1.180 J2.48 J2.84 J2.98 J2.112 J2.118 J19.1 J19.2 J21.32
ADC_POT1_OUT: J18.2 R95.2
ADC_POT2_OUT: J22.2 R96.2
GPIO91: J1.123 J24.2
HSEC_41: J2.41 J6.15
HSEC_43: J2.43 J6.16
HSEC_44: J2.44 J12.15
HSEC_45: J2.45 J6.17
HSEC_66: J2.66 J21.9
HSEC_88: J2.88 J21.19
HSEC_96: J2.96 J21.23
HSEC_113: J2.113 J20.29
HSEC_114: J2.114 J21.30
HSEC_115: J2.115 J20.30
HSEC_116: J2.116 J21.31
HSEC_117: J2.117 J20.31
HSEC_119: J2.119 J20.32
HSEC_136: J1.136 J25.8
HSEC_171: J1.171 J24.24
HSEC_172: J1.172 J25.25
HSEC_173: J1.173 J24.25
HSEC_174: J1.174 J25.26
HSEC_175: J1.175 J24.26
HSEC_176: J1.176 J25.27
HSEC_177: J1.177 J24.27
HSEC_ADC0_AIN0: J2.9 J6.1 J18.1 J65.1
HSEC_ADC0_AIN1: J2.11 J6.2 J22.1 J66.1
HSEC_ADC0_AIN2: J2.15 J6.4
HSEC_ADC0_AIN3: J2.17 J6.5
HSEC_ADC0_AIN4: J2.21 J6.6
HSEC_ADC0_AIN5: J2.23 J6.7
HSEC_ADC1_AIN0: J2.12 J12.1
HSEC_ADC1_AIN1: J2.14 J12.2
HSEC_ADC1_AIN2: J2.18 J12.4
HSEC_ADC1_AIN3: J2.20 J12.5
HSEC_ADC1_AIN4: J2.24 J12.6
HSEC_ADC1_AIN5: J2.26 J12.7
HSEC_ADC2_AIN0: J2.31 J6.11
HSEC_ADC2_AIN1: J2.33 J6.12
HSEC_ADC2_AIN2: J2.37 J6.13
HSEC_ADC2_AIN3: J2.39 J6.14
HSEC_ADC3_AIN0: J2.28 J12.8
HSEC_ADC3_AIN1: J2.30 J12.9
HSEC_ADC3_AIN2: J2.34 J12.11
HSEC_ADC3_AIN3: J2.36 J12.12
HSEC_ADC3_AIN4: J2.40 J12.13
HSEC_ADC3_AIN5: J2.42 J12.14
HSEC_ADC4_AIN0: J2.25 J6.8
HSEC_ADC4_AIN1: J2.27 J6.9
HSEC_EPWM3_B: J2.56 J21.4
HSEC_EPWM4_A: J2.57 J20.5
HSEC_EPWM4_B: J2.59 J20.6
HSEC_EPWM5_A: J2.61 J20.7
HSEC_EPWM5_B: J2.63 J20.8
HSEC_EPWM6_A: J2.58 J21.5
HSEC_EPWM6_B: J2.60 J21.6
HSEC_EPWM7_A: J2.62 J21.7
HSEC_EPWM7_B: J2.64 J21.8
HSEC_EPWM21_A: J2.89 J20.19
HSEC_EPWM21_B: J2.90 J21.20
HSEC_EQEP0_A: J2.102 J21.25
HSEC_EQEP0_B: J2.100 J21.24
HSEC_EQEP0_INDEX: J2.106 J21.27
HSEC_EQEP0_STROBE: J2.104 J21.26
HSEC_EQEP1_INDEX: J2.74 J21.13
HSEC_EQEP1_STROBE: J2.72 J21.12
HSEC_EQEP2_A: J2.92 J21.21
HSEC_EQEP2_B: J2.93 J20.21
HSEC_GPIO43: J2.49 J20.1 ; off-sheet HSEC_GPIO43
HSEC_GPIO44: J2.51 J20.2 ; off-sheet HSEC_GPIO44
HSEC_GPIO45: J2.53 J20.3 ; off-sheet HSEC_GPIO45
HSEC_GPIO46: J2.55 J20.4 ; off-sheet HSEC_GPIO46
HSEC_GPIO47: J2.50 J21.1 ; off-sheet HSEC_GPIO47
HSEC_GPIO48: J2.52 J21.2 ; off-sheet HSEC_GPIO48
HSEC_GPIO49: J2.54 J21.3 ; off-sheet HSEC_GPIO49
HSEC_GPIO65: J2.86 J21.18
HSEC_GPMC0_A0: J25.2 R29.2 ; off-sheet HSEC_GPMC0_A0
HSEC_GPMC0_A1: J24.3 R30.1 ; off-sheet HSEC_GPMC0_A1
HSEC_GPMC0_A2: J25.3 R31.2 ; off-sheet HSEC_GPMC0_A2
HSEC_GPMC0_A3: J24.4 R32.1 ; off-sheet HSEC_GPMC0_A3
HSEC_GPMC0_A4: J25.4 R33.2 ; off-sheet HSEC_GPMC0_A4
HSEC_GPMC0_A5: J24.5 R34.1 ; off-sheet HSEC_GPMC0_A5
HSEC_GPMC0_A6: J25.5 R35.2 ; off-sheet HSEC_GPMC0_A6
HSEC_GPMC0_A7: J24.6 R40.1 ; off-sheet HSEC_GPMC0_A7
HSEC_GPMC0_A8: J25.6 R41.2 ; off-sheet HSEC_GPMC0_A8
HSEC_GPMC0_A9: J24.7 R42.1 ; off-sheet HSEC_GPMC0_A9
HSEC_GPMC0_A10: J25.7 R43.2 ; off-sheet HSEC_GPMC0_A10
HSEC_GPMC0_A11_TRC_DATA4: J24.10 R98.1 ; off-sheet HSEC_GPMC0_A11_TRC_DATA4
HSEC_GPMC0_A12_TRC_DATA5: J25.11 R99.2 ; off-sheet HSEC_GPMC0_A12_TRC_DATA5
HSEC_GPMC0_A13_TRC_DATA6: J24.11 R100.1 ; off-sheet HSEC_GPMC0_A13_TRC_DATA6
HSEC_GPMC0_A14_TRC_DATA7: J25.12 R101.2 ; off-sheet HSEC_GPMC0_A14_TRC_DATA7
HSEC_GPMC0_A15_TRC_DATA8: J24.12 R102.1 ; off-sheet HSEC_GPMC0_A15_TRC_DATA8
HSEC_GPMC0_A16_TRC_DATA9: J25.13 R103.2 ; off-sheet HSEC_GPMC0_A16_TRC_DATA9
HSEC_GPMC0_A17_TRC_DATA10: J24.13 R104.1 ; off-sheet HSEC_GPMC0_A17_TRC_DATA10
HSEC_GPMC0_A18_TRC_DATA11: J25.14 R105.2 ; off-sheet HSEC_GPMC0_A18_TRC_DATA11
HSEC_GPMC0_A19_TRC_DATA12: J24.14 R106.1 ; off-sheet HSEC_GPMC0_A19_TRC_DATA12
HSEC_GPMC0_A20_TRC_DATA13: J25.15 R107.2 ; off-sheet HSEC_GPMC0_A20_TRC_DATA13
HSEC_GPMC0_A21_TRC_DATA14: J24.15 R108.1 ; off-sheet HSEC_GPMC0_A21_TRC_DATA14
HSEC_GPMC0_AD0: J24.16 R110.1 ; off-sheet HSEC_GPMC0_AD0
HSEC_GPMC0_AD1: J25.17 R111.2 ; off-sheet HSEC_GPMC0_AD1
HSEC_GPMC0_AD2: J24.17 R112.1 ; off-sheet HSEC_GPMC0_AD2
HSEC_GPMC0_AD3: J25.18 R113.2 ; off-sheet HSEC_GPMC0_AD3
HSEC_GPMC0_AD4: J24.18 R114.1 ; off-sheet HSEC_GPMC0_AD4
HSEC_GPMC0_AD5: J25.19 R115.2 ; off-sheet HSEC_GPMC0_AD5
HSEC_GPMC0_AD6: J24.19 R116.1 ; off-sheet HSEC_GPMC0_AD6
HSEC_GPMC0_AD7: J25.20 R117.2 ; off-sheet HSEC_GPMC0_AD7
HSEC_GPMC0_AD8: J24.20 R118.1 ; off-sheet HSEC_GPMC0_AD8
HSEC_GPMC0_AD9: J25.21 R119.2 ; off-sheet HSEC_GPMC0_AD9
HSEC_GPMC0_AD10: J24.21 R120.1 ; off-sheet HSEC_GPMC0_AD10
HSEC_GPMC0_AD11: J25.22 R121.2 ; off-sheet HSEC_GPMC0_AD11
HSEC_GPMC0_AD12: J24.22 R122.1 ; off-sheet HSEC_GPMC0_AD12
HSEC_GPMC0_AD13: J25.23 R123.2 ; off-sheet HSEC_GPMC0_AD13
HSEC_GPMC0_AD14: J24.23 R124.1 ; off-sheet HSEC_GPMC0_AD14
HSEC_GPMC0_AD15: J25.24 R125.2 ; off-sheet HSEC_GPMC0_AD15
HSEC_GPMC0_BE0N_CLE_TRC_DATA1: J25.9 R45.2 ; off-sheet HSEC_GPMC0_BE0N_CLE_TRC_DATA1
HSEC_GPMC0_BEN1_TRC_DATA2: J24.9 R46.1 ; off-sheet HSEC_GPMC0_BEN1_TRC_DATA2
HSEC_GPMC0_CLK: J2.110 J21.29 ; off-sheet HSEC_GPMC0_CLK
HSEC_GPMC0_CSN0_TRC_DATA15: J25.16 R109.2 ; off-sheet HSEC_GPMC0_CSN0_TRC_DATA15
HSEC_GPMC0_OEN_REN_TRC_DATA0: J24.8 R44.1 ; off-sheet HSEC_GPMC0_OEN_REN_TRC_DATA0
HSEC_GPMC0_WAIT0: J24.1 R27.1 ; off-sheet HSEC_GPMC0_WAIT0
HSEC_GPMC0_WEN_TRC_DATA3: J25.10 R97.2 ; off-sheet HSEC_GPMC0_WEN_TRC_DATA3
HSEC_GPMC0_WPN: J25.1 R28.2 ; off-sheet HSEC_GPMC0_WPN
HSEC_I2C1_SCL: J2.87 J20.18
HSEC_I2C1_SDA: J2.85 J20.17
HSEC_LIN1_RXD: J2.76 J21.14 ; off-sheet HSEC_LIN1_RXD
HSEC_LIN1_TXD: J2.78 J21.15 ; off-sheet HSEC_LIN1_TXD
HSEC_LIN3_RXD: J2.73 J20.12 ; off-sheet HSEC_LIN3_RXD
HSEC_LIN3_TXD: J2.71 J20.11 ; off-sheet HSEC_LIN3_TXD
HSEC_MCAN0_RX: J2.80 J21.16 ; off-sheet HSEC_MCAN0_RX
HSEC_MCAN0_TX: J2.82 J21.17 ; off-sheet HSEC_MCAN0_TX
HSEC_MCAN2_RX: J2.94 J21.22 ; off-sheet HSEC_MCAN2_RX
HSEC_MCAN2_TX: J2.95 J20.22 ; off-sheet HSEC_MCAN2_TX
HSEC_MII0_RXER: J2.108 J21.28
HSEC_PORz: J2.120 J21.33
HSEC_SAFETY_ERROR: J1.178 J25.28
HSEC_SDFM0_CLK1: J2.101 J20.24
HSEC_SDFM0_CLK2: J2.105 J20.26
HSEC_SDFM0_CLK3: J2.109 J20.28
HSEC_SDFM0_D0: J2.91 J20.20
HSEC_SDFM0_D1: J2.99 J20.23
HSEC_SDFM0_D2: J2.103 J20.25
HSEC_SDFM0_D3: J2.107 J20.27
HSEC_SPI0_D0: J2.67 J20.9
HSEC_SPI0_D1: J2.69 J20.10
HSEC_SPI1_CLK: J2.79 J20.15
HSEC_SPI1_CS0: J2.81 J20.16
HSEC_SPI1_D0: J2.75 J20.13
HSEC_SPI1_D1: J2.77 J20.14
HSEC_TCK: J2.5 ; off-sheet HSEC_TCK
HSEC_TDI: J2.8 ; off-sheet HSEC_TDI
HSEC_TDO: J2.6 ; off-sheet HSEC_TDO
HSEC_TMS: J2.3 ; off-sheet HSEC_TMS
HSEC_TRC_CLK: J21.10 R24.2 ; off-sheet HSEC_TRC_CLK
HSEC_TRC_CTL: J21.11 R26.2 ; off-sheet HSEC_TRC_CTL
OPAMP1_IN: J18.3 U16.3(IN+)
OPAMP1_OUT: C30.2 J65.2 U16.1(OUT) U16.2(IN-)
OPAMP2_IN: J22.3 U16.5(IN+)
OPAMP2_OUT: C41.2 J66.2 U16.6(IN-) U16.7(OUT)
NetJ1_121: J1.121 R27.2
NetJ1_122: J1.122 R28.1
NetJ1_124: J1.124 R29.1
NetJ1_125: J1.125 R30.2
NetJ1_126: J1.126 R31.1
NetJ1_127: J1.127 R32.2
NetJ1_128: J1.128 R33.1
NetJ1_129: J1.129 R34.2
NetJ1_130: J1.130 R35.1
NetJ1_131: J1.131 R40.2
NetJ1_132: J1.132 R41.1
NetJ1_133: J1.133 R42.2
NetJ1_134: J1.134 R43.1
NetJ1_137: J1.137 R44.2
NetJ1_138: J1.138 R45.1
NetJ1_139: J1.139 R46.2
NetJ1_140: J1.140 R97.1
NetJ1_141: J1.141 R98.2
NetJ1_142: J1.142 R99.1
NetJ1_143: J1.143 R100.2
NetJ1_144: J1.144 R101.1
NetJ1_145: J1.145 R102.2
NetJ1_146: J1.146 R103.1
NetJ1_147: J1.147 R104.2
NetJ1_148: J1.148 R105.1
NetJ1_149: J1.149 R106.2
NetJ1_150: J1.150 R107.1
NetJ1_151: J1.151 R108.2
NetJ1_152: J1.152 R109.1
NetJ1_153: J1.153 R110.2
NetJ1_154: J1.154 R111.1
NetJ1_155: J1.155 R112.2
NetJ1_156: J1.156 R113.1
NetJ1_159: J1.159 R114.2
NetJ1_160: J1.160 R115.1
NetJ1_161: J1.161 R116.2
NetJ1_162: J1.162 R117.1
NetJ1_163: J1.163 R118.2
NetJ1_164: J1.164 R119.1
NetJ1_165: J1.165 R120.2
NetJ1_166: J1.166 R121.1
NetJ1_167: J1.167 R122.2
NetJ1_168: J1.168 R123.1
NetJ1_169: J1.169 R124.2
NetJ1_170: J1.170 R125.1
NetJ2_68: J2.68 R24.1
NetJ2_70: J2.70 R26.1

Not connected (* = marked no-connect by the designer): J2 1* 2* 4*; R95 4(MNT_1)* 5(MNT_2)*; R96 4(MNT_1)* 5(MNT_2)*

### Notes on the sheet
- Place ground return pins 1:1 with ADC channels
- 180-Pin HSEC Connector
- Off-sheet connected signals are used in breakout board peripherals. All HSEC signals are to be broken out to 100mil headers.
- Off-sheet Connections
- (near J31) Place GND return pins 1:4 with HSEC signals.  DNP J31, J32
- ADC Channel Variable Resistors
- SH-J1 connect J18-2 and J18-3 by default
- SH-J2 connect J22-2 and J22-3 by default
- ADC Signal Conditioning
- Place GND return pins 1:4 with HSEC signals
- SH-J3 connect J65-1 and J65-2 by default
- SH-J4 connect J65-1 and J65-2 by default

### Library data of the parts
C30 C41 = CMP-0120357-1: 300 pF ±5% 50V Ceramic Capacitor C0G, NP0 0603 (1608 Metric); Manufacturer: KEMET; AEC Qualified: No; SizeZ_mm: 0.87mm; TempCo: 30ppm/°C; Value: 300pF
J1 = CMP-0003859-2: C2000 controlCARD-180HSEC (60-pin addon) connector, SMT; Manufacturer: Samtec; Note: The pin numbering does not match Samtec datasheet
J2 = CMP-0003814-2: C2000 controlCARD-120HSEC connector, SMT; Manufacturer: Samtec; Note: The pin numbering does not match Samtec datasheet
J6 J14 = CMP-02766-001472-1: CONN HEADER VERT 17POS 2.54MM; Manufacturer: Samtec; Number of Positions: 17; Connector Type: Male Pin; Pitch: 0.1inch; Gender: Male
J12 J15 = CMP-02766-001466-1: CONN HEADER VERT 15POS 2.54MM; Manufacturer: Samtec; Connector Type: Male Pin; Number of Contacts: 15; Gender: Male; Pitch: 0.1inch
J13 J16 J17 J19 J23 J26-J30 J65 J66 = CMP-0077643-1: Header, 2.54mm, 2x1, Gold, TH; Manufacturer: Samtec; Pitch_mm: 2.54; Gender: Male; Cert_CSA: Y; Current_A: 5.7A; Voltage_V: 550V; Row_Count: 1
J18 J22 = CMP-0055332-1: Header, 2.54mm, 3x1, Tin, TH; Manufacturer: Molex; CNHeader: TRUE; Current_A: 4A; Shrouded: N; Gender: Male; Voltage_V: 250V; Row_Count: 1; Pitch_mm: 2.54; CT: FALSE; Cert_UL: Y
J20 = CMP-02766-001470-1: CONN HEADER VERT 32POS 2.54MM; Manufacturer: Samtec; Number of Contacts: 32; Connector Type: Male Pin; Gender: Male; Pitch: 0.1inch
J21 = CMP-02766-001386-1: CONN HEADER VERT 33POS 2.54MM; Manufacturer: Samtec; Connector Type: Male Pin; Number of Positions: 33; Pitch: 0.1inch; Gender: Male
J24 = CMP-02766-001392-1: CONN HEADER VERT 27POS 2.54MM; Manufacturer: Samtec; Pitch: 0.1inch; Gender: Male; Number of Positions: 27; Connector Type: Male Pin
J25 = CMP-02766-001385-1: CONN HEADER VERT 28POS 2.54MM; Manufacturer: Samtec; Number of Contacts: 28; Connector Type: Male Pin; Gender: Male; Pitch: 0.1inch
J31-J64 = CMP-0079328-1: Header, 2.54mm, 1x1, Gold, TH; Manufacturer: Samtec; Gender: Male; Cert_UL: Y; Shrouded: N; Row_Count: 1
R24 R26-R35 R40-R46 R97-R125 = CMP-0027309-2: RES, 10.0, 1%, 0.05 W, 0201; Manufacturer: Yageo America; Power_W: 50mW; TempCo: 350 ppm/C; Value_Code: 10R0; U/M: EA; Value: 10.0; EIA_Code: E96; Res_ohm: 10; SizeX_mm: 0.6; SizeY_mm: 0.3; SizeZ_mm: 0.26; Value2: 0.05W; SizeArea_mm2: 0.18; AEC Qualified: N; VDC_V: 25V; AEC Category: Q200
R95 R96 = CMP-0096228-1: 10k Ohm 1 Gang Linear Through Hole, Snap In Potentiometer None 1.0 Kierros Carbon 0.05W, 1/20W PC Pins, Board Locks; Manufacturer: Bourns; Res_ohm: 10kΩ; Tolerance_%: 20%; AEC Qualified: No; VDC_V: 20V; SizeZ_mm: 15.5mm; Value: 10kΩ
U16 = CMP-0013309-4: OPA2837DGK, DGK0008A (VSSOP-8); Manufacturer: Texas Instruments; SizeX_mm: 4.9; SizeY_mm: 3; CompType: IC; SizeZ_mm: 1.1; SizeArea_mm2: 14.7; SizeAreaWB_mm2: 23.6; AEC Category: Q200; AEC Qualified: N

## Sheet PROC148A_CAN_LIN.SchDoc
size 431 x 279 mm; Date: Not shown in title block; ApprovedBy: Not shown in title block; CheckedBy: Not shown in title block; Author: Not shown in title block; CompanyName: Not shown in title block; Engineer: Not shown in title block; Organization: Not shown in title block; Address1: Not shown in title block; Address2: Not shown in title block; Address3: Not shown in title block; Address4: Not shown in title block; DocumentNumber: 1; Revision: Use project parameter SCH_Rev; SheetNumber: 4; SheetTotal: 9; PageSetup: Record=PageOptions¦CenterHorizontal=True¦CenterVertical=True¦PrintScale=1.00¦XCorrection=1.00¦YCorrection=1.00¦PrintKind=0¦BorderSize=5000000¦LeftOffset=0¦BottomOffset=0¦Orientation=2¦PaperLength=1000¦PaperWidth=1000¦Scale=100¦PaperSource=15¦PrintQuality=600¦MediaType=1¦DitherType=10¦PaperKind=Letter¦PrintScaleMode=1
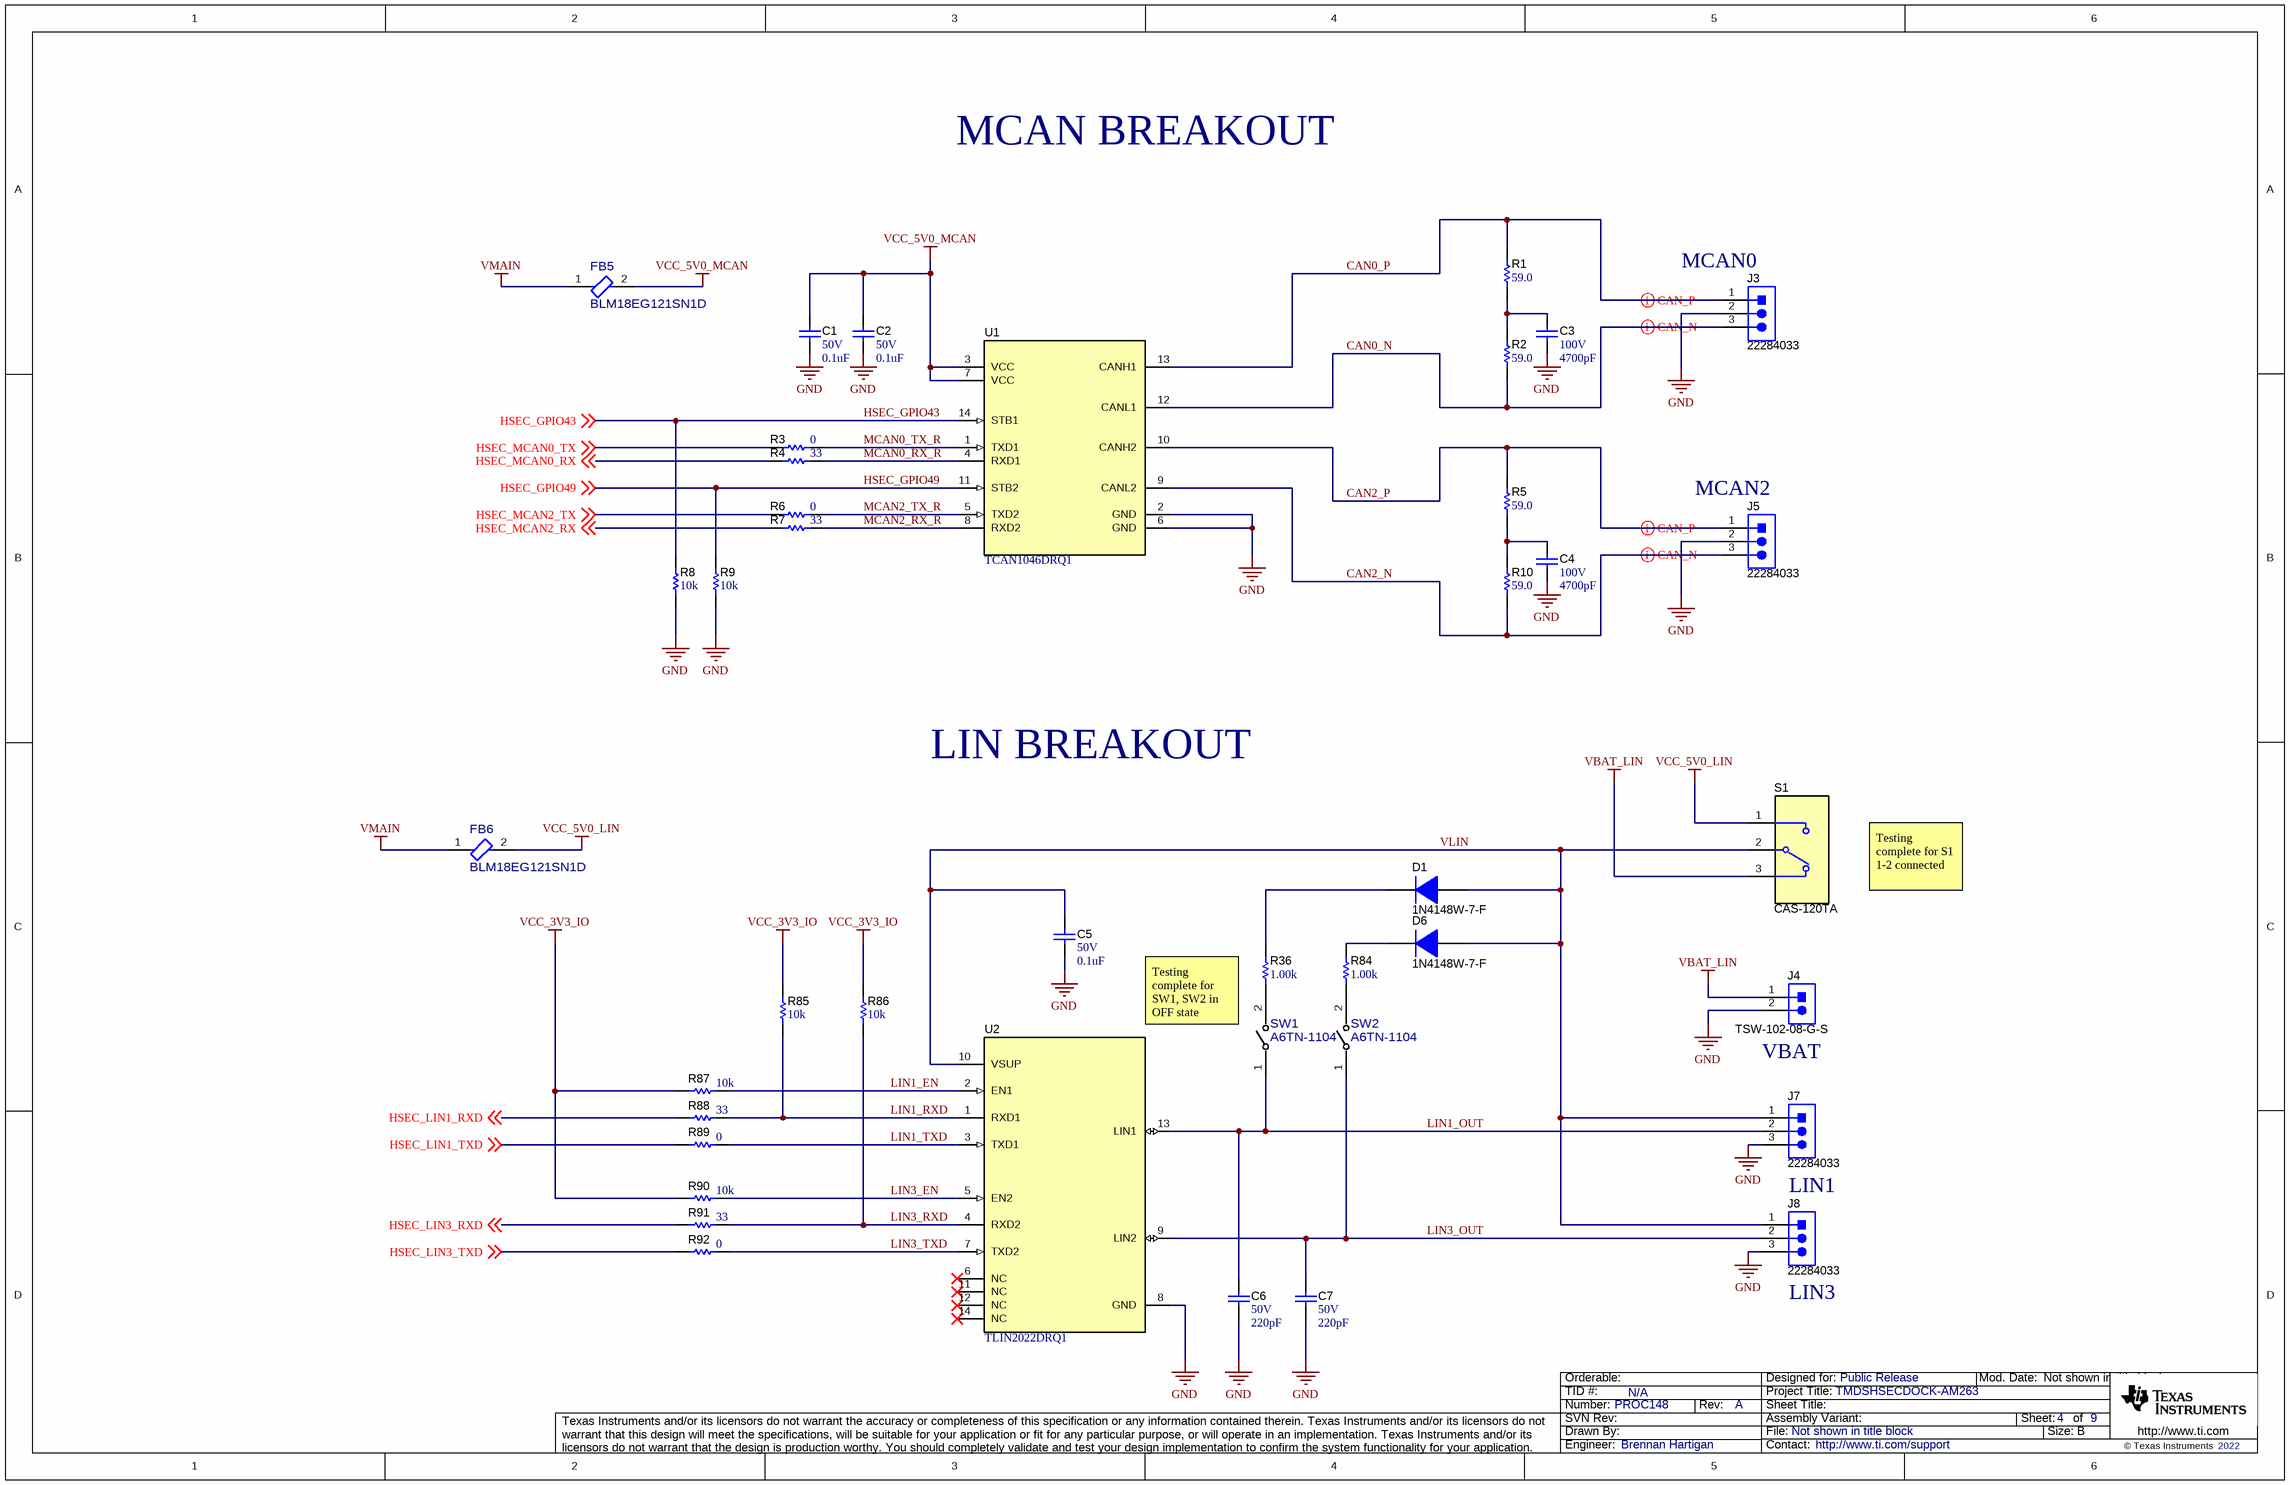
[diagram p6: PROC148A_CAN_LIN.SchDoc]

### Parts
C1  VDC_V: 50V  ValueDisplayed: 0.1uF  [0402]  (hidden comment: GRM155R71H104ME14D)
C2  VDC_V: 50V  ValueDisplayed: 0.1uF  [0402]  (hidden comment: GRM155R71H104ME14D)
C3  VDC_V: 100V  ValueDisplayed: 4700pF  [0402]  (hidden comment: GRM155R72A472KA01D)
C4  VDC_V: 100V  ValueDisplayed: 4700pF  [0402]  (hidden comment: GRM155R72A472KA01D)
C5  VDC_V: 50V  ValueDisplayed: 0.1uF  [0402]  (hidden comment: GRM155R71H104ME14D)
C6  VDC_V: 50V  ValueDisplayed: 220pF  [0402]  (hidden comment: CGA2B2X8R1H221K050BA)
C7  VDC_V: 50V  ValueDisplayed: 220pF  [0402]  (hidden comment: CGA2B2X8R1H221K050BA)
D1  1N4148W-7-F  [SOD-123]
D6  1N4148W-7-F  [SOD-123]
FB5  BLM18EG121SN1D  [FP-BLM18EG121SN1D_0603-MFG]
FB6  BLM18EG121SN1D  [FP-BLM18EG121SN1D_0603-MFG]
J3  22284033  [Molex_0022284033]
J4  TSW-102-08-G-S  [Samtec_TSW-102-08-x-S]
J5  22284033  [Molex_0022284033]
J7  22284033  [Molex_0022284033]
J8  22284033  [Molex_0022284033]
R1  ValueDisplayed: 59.0  [0402]  (hidden comment: CRCW040259R0FKED)
R2  ValueDisplayed: 59.0  [0402]  (hidden comment: CRCW040259R0FKED)
R3  ValueDisplayed: 0  [0402]  (hidden comment: CRCW04020000Z0ED)
R4  ValueDisplayed: 33  [0402]  (hidden comment: CRCW040233R0JNED)
R5  ValueDisplayed: 59.0  [0402]  (hidden comment: CRCW040259R0FKED)
R6  ValueDisplayed: 0  [0402]  (hidden comment: CRCW04020000Z0ED)
R7  ValueDisplayed: 33  [0402]  (hidden comment: CRCW040233R0JNED)
R8  ValueDisplayed: 10k  [0402]  (hidden comment: ERJ-2GEJ103X)
R9  ValueDisplayed: 10k  [0402]  (hidden comment: ERJ-2GEJ103X)
R10  ValueDisplayed: 59.0  [0402]  (hidden comment: CRCW040259R0FKED)
R36  ValueDisplayed: 1.00k  [0402]  (hidden comment: CRCW04021K00FKED)
R84  ValueDisplayed: 1.00k  [0402]  (hidden comment: CRCW04021K00FKED)
R85  ValueDisplayed: 10k  [0402]  (hidden comment: CRCW040210K0JNED)
R86  ValueDisplayed: 10k  [0402]  (hidden comment: CRCW040210K0JNED)
R87  ValueDisplayed: 10k  [0402]  (hidden comment: CRCW040210K0JNED)
R88  ValueDisplayed: 33  [0402]  (hidden comment: CRCW040233R0JNED)
R89  ValueDisplayed: 0  [0402]  (hidden comment: CRCW04020000Z0ED)
R90  ValueDisplayed: 10k  [0402]  (hidden comment: CRCW040210K0JNED)
R91  ValueDisplayed: 33  [0402]  (hidden comment: CRCW040233R0JNED)
R92  ValueDisplayed: 0  [0402]  (hidden comment: CRCW04020000Z0ED)
S1  CAS-120TA  [SW_CAS-120TA]
SW1  A6TN-1104  [FP-A6TN-1104_PTH_SW_7MM50_4MM48-MFG]
SW2  A6TN-1104  [FP-A6TN-1104_PTH_SW_7MM50_4MM48-MFG]
U1  TCAN1046DRQ1  [D0014A_N]
U2  TLIN2022DRQ1  [D0014A_N]

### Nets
GND: C1.2 C2.2 C3.2 C4.2 C5.2 C6.2 C7.2 J3.2 J4.2 J5.2 J7.3 J8.3 R8.1 R9.1 U1.2(GND) U1.6(GND) U2.8(GND)
VBAT_LIN: J4.1 S1.3
VCC_3V3_IO: R85.2 R86.2 R87.1 R90.1
VCC_5V0_LIN: FB6.2 S1.1
VCC_5V0_MCAN: C1.1 C2.1 FB5.2 U1.3(VCC) U1.7(VCC)
VMAIN: FB5.1 FB6.1
CAN0_N: J3.3 R2.1 U1.12(CANL1)
CAN0_P: J3.1 R1.2 U1.13(CANH1)
CAN2_N: J5.3 R10.1 U1.9(CANL2)
CAN2_P: J5.1 R5.2 U1.10(CANH2)
HSEC_GPIO43: R8.2 U1.14(STB1) ; off-sheet HSEC_GPIO43
HSEC_GPIO49: R9.2 U1.11(STB2) ; off-sheet HSEC_GPIO49
HSEC_LIN1_RXD: R88.1 ; off-sheet HSEC_LIN1_RXD
HSEC_LIN1_TXD: R89.1 ; off-sheet HSEC_LIN1_TXD
HSEC_LIN3_RXD: R91.1 ; off-sheet HSEC_LIN3_RXD
HSEC_LIN3_TXD: R92.1 ; off-sheet HSEC_LIN3_TXD
HSEC_MCAN0_RX: R4.1 ; off-sheet HSEC_MCAN0_RX
HSEC_MCAN0_TX: R3.1 ; off-sheet HSEC_MCAN0_TX
HSEC_MCAN2_RX: R7.1 ; off-sheet HSEC_MCAN2_RX
HSEC_MCAN2_TX: R6.1 ; off-sheet HSEC_MCAN2_TX
LIN1_EN: R87.2 U2.2(EN1)
LIN1_OUT: C6.1 J7.2 SW1.1 U2.13(LIN1)
LIN1_RXD: R85.1 R88.2 U2.1(RXD1)
LIN1_TXD: R89.2 U2.3(TXD1)
LIN3_EN: R90.2 U2.5(EN2)
LIN3_OUT: C7.1 J8.2 SW2.1 U2.9(LIN2)
LIN3_RXD: R86.1 R91.2 U2.4(RXD2)
LIN3_TXD: R92.2 U2.7(TXD2)
MCAN0_RX_R: R4.2 U1.4(RXD1)
MCAN0_TX_R: R3.2 U1.1(TXD1)
MCAN2_RX_R: R7.2 U1.8(RXD2)
MCAN2_TX_R: R6.2 U1.5(TXD2)
VLIN: C5.1 D1.2(A) D6.2(A) J7.1 J8.1 S1.2 U2.10(VSUP)
NetC3_1: C3.1 R1.1 R2.2
NetC4_1: C4.1 R5.1 R10.2
NetD1_1: D1.1(K) R36.2
NetD6_1: D6.1(K) R84.2
NetR36_1: R36.1 SW1.2
NetR84_1: R84.1 SW2.2

Not connected (* = marked no-connect by the designer): U2 6(NC)* 11(NC)* 12(NC)* 14(NC)*

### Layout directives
differential pair: CAN0_N, CAN0_P, CAN2_N, CAN2_P

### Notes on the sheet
- MCAN BREAKOUT
- (near J3) MCAN0
- (near J5) MCAN2
- LIN BREAKOUT
- Testing complete for S1 1-2 connected
- Testing complete for SW1, SW2 in OFF state
- (near J4) VBAT
- LIN1
- (near J8) LIN3

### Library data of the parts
C1 C2 C5 = CMP-0006675-2: CAP, CERM, 0.1 uF, 50 V, +/- 20%, X7R, 0402; Manufacturer: MuRata; TaMin_C: -55°C; Polarized: N; SizeAreaWB_mm2: 3; Value1: Unknown; U/M: EA; Value: 0.1uF; TaMax_C: 125°C; SizeZ_mm: 0.6; SizeX_mm: 1; SizeY_mm: 0.5; Cap_F: 100nF; AEC Category: Q200
C3 C4 = CMP-0006712-2: CAP, CERM, 4700 pF, 100 V, +/- 10%, X7R, 0402; Manufacturer: MuRata; TaMin_C: -55°C; Polarized: N; SizeAreaWB_mm2: 3; Value1: Unknown; U/M: EA; Value: 4700pF; TaMax_C: 125°C; SizeZ_mm: 0.6; SizeX_mm: 1; SizeY_mm: 0.5; Cap_F: 4.7nF; AEC Category: Q200
C6 C7 = CMP-0084239-1: CAP, CERM, 220 pF, 50 V,+/- 10%, X8R, AEC-Q200 Grade 0, 0402; Manufacturer: TDK; TaMin_C: -55°C; Polarized: N; SizeAreaWB_mm2: 3; U/M: EA; Value: 220pF; TaMax_C: 150°C; SizeZ_mm: 0.6; SizeX_mm: 1; SizeY_mm: 0.5; AEC Qualified: Y; AEC Grade: 0; AEC Category: Q200
D1 D6 = CMP-0029001-2: Diode, Ultrafast, 100 V, 0.15 A, SOD-123; Manufacturer: Diodes Inc.; SizeX_mm: 3.85; Value2: 1.25V; Green_REACh: Passed; TJmax_C: 150°C; AEC Category: Q101; SizeAreaWB_mm2: 13.095; Value: 100V; Green_Lifecycle: Active; SizeY_mm: 1.7; Value1: 0.15A; SizeArea_mm2: 6.545; Io_A: 150mA; SizeZ_mm: 1.35
FB5 FB6 = CMP-0089199-1: as FB4 on sheet PROC148A_PWR
J3 J5 J7 J8 = CMP-0055332-1: as J18 on sheet PROC148A_HSEC
J4 = CMP-0077643-1: as J13 on sheet PROC148A_HSEC
R1 R2 R5 R10 = CMP-0026462-2: RES, 59.0, 1%, 0.063 W, AEC-Q200 Grade 0, 0402; Manufacturer: Vishay-Dale; Power_W: 63mW; TempCo: 100 ppm/C; Value_Code: 59R0; Value: 59.0; EIA_Code: E96; Res_ohm: 59; SizeX_mm: 1; SizeY_mm: 0.5; Value2: 0.063W; AEC Qualified: Y; VDC_V: 50V; AEC Category: Q200; AEC Grade: 0; SizeZ_mm: 0.6
R3 R6 R89 R92 = CMP-0026822-3: as R53 on sheet PROC148A_PWR
R4 R7 R88 R91 = CMP-0026908-3: RES, 33, 5%, 0.063 W, AEC-Q200 Grade 0, 0402; Manufacturer: Vishay-Dale; Power_W: 63mW; TempCo: 200 ppm/C; Value_Code: 33R0; Value: 33; EIA_Code: E24; SizeX_mm: 1; SizeY_mm: 0.5; SizeZ_mm: 0.6; Value2: 0.063W; AEC Qualified: Y; VDC_V: 50V; AEC Category: Q200; AEC Grade: 0
R8 R9 = CMP-0026994-4: RES, 10 k, 5%, 0.1 W, AEC-Q200 Grade 0, 0402; Manufacturer: Panasonic; Power_W: 100mW; TempCo: 200 ppm/C; Value_Code: 10k0; U/M: EA; Value: 10k; EIA_Code: E24; SizeX_mm: 1; SizeY_mm: 0.5; SizeZ_mm: 0.6; Value2: 0.1W; AEC Qualified: Y; VDC_V: 50V; AEC Grade: 0; AEC Category: Q200
R36 R84 = CMP-0026071-3: RES, 1.00 k, 1%, 0.063 W, AEC-Q200 Grade 0, 0402; Manufacturer: Vishay-Dale; Power_W: 63mW; TempCo: 100 ppm/C; Value_Code: 1k00; Value: 1.00k; EIA_Code: E96; Res_ohm: 1k; SizeX_mm: 1; SizeY_mm: 0.5; SizeZ_mm: 0.6; Value2: 0.063W; AEC Qualified: Y; VDC_V: 50V; AEC Category: Q200; AEC Grade: 0
R85-R87 R90 = CMP-0026825-5: as R93 on sheet PROC148A_PWR
S1 = CMP-0002139-2: Switch, Slide, SPDT  100mA, SMT; Manufacturer: Copal Electronics; CurrentRating_mA: 100A; SwitchFunction: On-On; VDC_V: 6V; PositionCount: 1
SW1 SW2 = CMP-0086077-1: Dip Switch SPST 1 Position Through Hole Slide (Standard) Actuator 25mA 24VDC; Manufacturer: Omron Electronics Inc-EMC Div; SizeZ_mm: 6.7mm; PositionCount: 1
U1 = CMP-0074638-2: Automotive High Speed Dual CAN Transceiver, D0014A (SOIC-14); Manufacturer: Texas Instruments; SizeZ_mm: 1.75; SizeX_mm: 6.0; SizeY_mm: 8.65; SizeArea_mm2: 51.9; CompType: IC; U/M: EA; SizeAreaWB_mm2: 85.2
U2 = CMP-0077655-1: Automotive Dual LIN Transceiver, D0014A (SOIC-14); Alternate PartNumber: TLIN2022DTQ1; Alternate Manufacturer: Texas Instruments; SizeAreaWB_mm2: 85.2; SizeZ_mm: 1.75; SizeX_mm: 6.0; SizeY_mm: 8.65; SizeArea_mm2: 51.9; CompType: IC; AEC Qualified: Y; AEC Category: Q200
